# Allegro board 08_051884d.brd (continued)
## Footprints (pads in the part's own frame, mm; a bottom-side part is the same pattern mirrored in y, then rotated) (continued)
CNSMAL554W247H118
  rect 4.521x0.508 smd: 1(-2.261,0)
  rect 5.537x3.607 smd: 2(-2.769,2.261) 3(-2.769,-2.261)
  rect 2.642x6.756 smd: 4(-1.321,0)
CNSMASQ197H161
  rect 0.267x1.295 smd: 1(0,-3.051)
  custom 1.302x1.302 smd: 2(0,2.299)
CNTERCU
  rect 2.616x0.889 smd: 1(0,0)
DFN10_3X3_PAD2_38X1_64
  oval 0.254x0.889 smd: 1(-1,-1.555) 2(-0.5,-1.555) 3(0,-1.555) 4(0.5,-1.555) 5(1,-1.555) 6(1,1.555) 7(0.5,1.555) 8(0,1.555) 9(-0.5,1.555) 10(-1,1.555)
  rect 2.388x1.651 smd: PAD(0,0)
DIOSMJ5_0
  rect 2.286x1.88 smd: A(2.164,0) C(-2.164,0)
DQFN16_3_5X2_5_PAD2_15X1_15
  oval 0.889x0.229 smd: 1(-1.795,-0.25) 8(1.795,-0.25) 9(1.795,0.25) 16(-1.795,0.25)
  oval 0.229x0.889 smd: 2(-1.25,-1.294) 3(-0.75,-1.294) 4(-0.25,-1.294) 5(0.25,-1.294) 6(0.75,-1.294) 7(1.25,-1.294) 10(1.25,1.294) 11(0.75,1.294) 12(0.25,1.294) 13(-0.25,1.294) 14(-0.75,1.294) 15(-1.25,1.294)
  rect 1.905x0.991 smd: PAD(0,0)
F1206
  rect 1.143x2.032 smd: 1(-1.333,0) 2(1.333,0)
JUMPER0603_3P
  rect 1.194x1.092 smd: 1(-1.694,0) 2(0,0) 3(1.694,0)
L0201
  rect 0.178x0.33 smd: 1(-0.203,0) 2(0.203,0)
L0402
  rect 0.584x0.711 smd: 1(-0.475,0) 2(0.475,0)
L0603H28
  rect 1.041x0.991 smd: 1(-0.75,0) 2(0.75,0)
LCC4H210
  rect 1.27x2.286 smd: 1(-2.54,-3.556) 2(2.54,-3.556) 3(2.54,3.556) 4(-2.54,3.556)
LED0402_A
  rect 0.711x0.508 smd: A(0.555,0) C(-0.555,0)
LFBGA324
  round 0.356 smd: A1(-6.8,-6.8) A2(-6.8,-6) A3(-6.8,-5.2) A4(-6.8,-4.4) A5(-6.8,-3.6) A6(-6.8,-2.8) A7(-6.8,-2) A8(-6.8,-1.2) A9(-6.8,-0.4) A10(-6.8,0.4) A11(-6.8,1.2) A12(-6.8,2) A13(-6.8,2.8) A14(-6.8,3.6) A15(-6.8,4.4) A16(-6.8,5.2) A17(-6.8,6) A18(-6.8,6.8) B1(-6,-6.8) B2(-6,-6) B3(-6,-5.2) B4(-6,-4.4) B5(-6,-3.6) B6(-6,-2.8) B7(-6,-2) B8(-6,-1.2) B9(-6,-0.4) B10(-6,0.4) B11(-6,1.2) B12(-6,2) B13(-6,2.8) B14(-6,3.6) B15(-6,4.4) B16(-6,5.2) B17(-6,6) B18(-6,6.8) C1(-5.2,-6.8) C2(-5.2,-6) C3(-5.2,-5.2) C4(-5.2,-4.4) C5(-5.2,-3.6) C6(-5.2,-2.8) C7(-5.2,-2) C8(-5.2,-1.2) C9(-5.2,-0.4) C10(-5.2,0.4) C11(-5.2,1.2) C12(-5.2,2) C13(-5.2,2.8) C14(-5.2,3.6) C15(-5.2,4.4) C16(-5.2,5.2) C17(-5.2,6) C18(-5.2,6.8) D1(-4.4,-6.8) D2(-4.4,-6) D3(-4.4,-5.2) D4(-4.4,-4.4) D5(-4.4,-3.6) D6(-4.4,-2.8) D7(-4.4,-2) D8(-4.4,-1.2) D9(-4.4,-0.4) D10(-4.4,0.4) D11(-4.4,1.2) D12(-4.4,2) D13(-4.4,2.8) D14(-4.4,3.6) D15(-4.4,4.4) D16(-4.4,5.2) D17(-4.4,6) D18(-4.4,6.8) E1(-3.6,-6.8) E2(-3.6,-6) E3(-3.6,-5.2) E4(-3.6,-4.4) E5(-3.6,-3.6) E6(-3.6,-2.8) E7(-3.6,-2) E8(-3.6,-1.2) E9(-3.6,-0.4) E10(-3.6,0.4) E11(-3.6,1.2) E12(-3.6,2) E13(-3.6,2.8) E14(-3.6,3.6) E15(-3.6,4.4) E16(-3.6,5.2) E17(-3.6,6) E18(-3.6,6.8) F1(-2.8,-6.8) F2(-2.8,-6) F3(-2.8,-5.2) F4(-2.8,-4.4) F5(-2.8,-3.6) F6(-2.8,-2.8) F7(-2.8,-2) F8(-2.8,-1.2) F9(-2.8,-0.4) F10(-2.8,0.4) F11(-2.8,1.2) F12(-2.8,2) F13(-2.8,2.8) F14(-2.8,3.6) F15(-2.8,4.4) F16(-2.8,5.2) F17(-2.8,6) F18(-2.8,6.8) G1(-2,-6.8) G2(-2,-6) G3(-2,-5.2) G4(-2,-4.4) G5(-2,-3.6) G6(-2,-2.8) G7(-2,-2) G8(-2,-1.2) G9(-2,-0.4) G10(-2,0.4) G11(-2,1.2) G12(-2,2) G13(-2,2.8) G14(-2,3.6) G15(-2,4.4) G16(-2,5.2) G17(-2,6) G18(-2,6.8) H1(-1.2,-6.8) H2(-1.2,-6) H3(-1.2,-5.2) H4(-1.2,-4.4) H5(-1.2,-3.6) H6(-1.2,-2.8) H7(-1.2,-2) H8(-1.2,-1.2) H9(-1.2,-0.4) H10(-1.2,0.4) H11(-1.2,1.2) H12(-1.2,2) H13(-1.2,2.8) H14(-1.2,3.6) H15(-1.2,4.4) H16(-1.2,5.2) H17(-1.2,6) H18(-1.2,6.8) J1(-0.4,-6.8) J2(-0.4,-6) J3(-0.4,-5.2) J4(-0.4,-4.4) J5(-0.4,-3.6) J6(-0.4,-2.8) J7(-0.4,-2) J8(-0.4,-1.2) J9(-0.4,-0.4) J10(-0.4,0.4) J11(-0.4,1.2) J12(-0.4,2) J13(-0.4,2.8) J14(-0.4,3.6) J15(-0.4,4.4) J16(-0.4,5.2) J17(-0.4,6) J18(-0.4,6.8) K1(0.4,-6.8) K2(0.4,-6) K3(0.4,-5.2) K4(0.4,-4.4) K5(0.4,-3.6) K6(0.4,-2.8) K7(0.4,-2) K8(0.4,-1.2) K9(0.4,-0.4) K10(0.4,0.4) K11(0.4,1.2) K12(0.4,2) K13(0.4,2.8) K14(0.4,3.6) K15(0.4,4.4) K16(0.4,5.2) K17(0.4,6) K18(0.4,6.8) L1(1.2,-6.8) L2(1.2,-6) L3(1.2,-5.2) L4(1.2,-4.4) L5(1.2,-3.6) L6(1.2,-2.8) L7(1.2,-2) L8(1.2,-1.2) L9(1.2,-0.4) L10(1.2,0.4) L11(1.2,1.2) L12(1.2,2) L13(1.2,2.8) L14(1.2,3.6) L15(1.2,4.4) L16(1.2,5.2) L17(1.2,6) L18(1.2,6.8) M1(2,-6.8) M2(2,-6) M3(2,-5.2) M4(2,-4.4) M5(2,-3.6) M6(2,-2.8) M7(2,-2) M8(2,-1.2) M9(2,-0.4) M10(2,0.4) M11(2,1.2) M12(2,2) M13(2,2.8) M14(2,3.6) M15(2,4.4) M16(2,5.2) M17(2,6) M18(2,6.8) N1(2.8,-6.8) N2(2.8,-6) N3(2.8,-5.2) N4(2.8,-4.4) N5(2.8,-3.6) N6(2.8,-2.8) N7(2.8,-2) N8(2.8,-1.2) N9(2.8,-0.4) N10(2.8,0.4) N11(2.8,1.2) N12(2.8,2) N13(2.8,2.8) N14(2.8,3.6) N15(2.8,4.4) N16(2.8,5.2) N17(2.8,6) N18(2.8,6.8) P1(3.6,-6.8) P2(3.6,-6) P3(3.6,-5.2) P4(3.6,-4.4) P5(3.6,-3.6) P6(3.6,-2.8) P7(3.6,-2) P8(3.6,-1.2) P9(3.6,-0.4) P10(3.6,0.4) P11(3.6,1.2) P12(3.6,2) P13(3.6,2.8) P14(3.6,3.6) P15(3.6,4.4) P16(3.6,5.2) P17(3.6,6) P18(3.6,6.8) R1(4.4,-6.8) R2(4.4,-6) R3(4.4,-5.2) R4(4.4,-4.4) R5(4.4,-3.6) R6(4.4,-2.8) R7(4.4,-2) R8(4.4,-1.2) R9(4.4,-0.4) R10(4.4,0.4) R11(4.4,1.2) R12(4.4,2) R13(4.4,2.8) R14(4.4,3.6) R15(4.4,4.4) R16(4.4,5.2) R17(4.4,6) R18(4.4,6.8) T1(5.2,-6.8) T2(5.2,-6) T3(5.2,-5.2) T4(5.2,-4.4) T5(5.2,-3.6) T6(5.2,-2.8) T7(5.2,-2) T8(5.2,-1.2) T9(5.2,-0.4) T10(5.2,0.4) T11(5.2,1.2) T12(5.2,2) T13(5.2,2.8) T14(5.2,3.6) T15(5.2,4.4) T16(5.2,5.2) T17(5.2,6) T18(5.2,6.8) U1(6,-6.8) U2(6,-6) U3(6,-5.2) U4(6,-4.4) U5(6,-3.6) U6(6,-2.8) U7(6,-2) U8(6,-1.2) U9(6,-0.4) U10(6,0.4) U11(6,1.2) U12(6,2) U13(6,2.8) U14(6,3.6) U15(6,4.4) U16(6,5.2) U17(6,6) U18(6,6.8) V1(6.8,-6.8) V2(6.8,-6) V3(6.8,-5.2) V4(6.8,-4.4) V5(6.8,-3.6) V6(6.8,-2.8) V7(6.8,-2) V8(6.8,-1.2) V9(6.8,-0.4) V10(6.8,0.4) V11(6.8,1.2) V12(6.8,2) V13(6.8,2.8) V14(6.8,3.6) V15(6.8,4.4) V16(6.8,5.2) V17(6.8,6) V18(6.8,6.8)
LGA43
  rect 0.356x0.432 smd: 1(-2.375,-2.25) 2(-1.875,-2.25) 3(-1.375,-2.25) 4(-0.875,-2.25) 5(-0.375,-2.25) 6(0.125,-2.25) 7(0.625,-2.25) 8(1.125,-2.25) 9(1.625,-2.25) 20(1.625,2.25) 21(1.125,2.25) 22(0.625,2.25) 23(0.125,2.25) 24(-0.375,2.25) 25(-0.875,2.25) 26(-1.375,2.25) 27(-1.875,2.25) 28(-2.375,2.25)
  rect 0.762x0.356 smd: 10(2.3,-2.25) 11(2.3,-1.75) 12(2.3,-1.25) 13(2.3,-0.75) 14(2.3,-0.25) 15(2.3,0.25) 16(2.3,0.75) 17(2.3,1.25) 18(2.3,1.75) 19(2.3,2.25)
  rect 0.864x0.254 smd: 29(-2.21,1.675) 30(-1.16,1.675) 31(-0.11,1.675) 41(-2.21,-1.675) 42(-1.16,-1.675) 43(-0.11,-1.675)
  rect 0.864x0.508 smd: 32(-2.21,0.925) 33(-1.16,0.925) 34(-0.11,0.925) 38(-2.21,-0.925) 39(-1.16,-0.925) 40(-0.11,-0.925)
  rect 0.864x0.61 smd: 35(-2.21,0) 36(-1.16,0) 37(-0.11,0)
LSML208W216H122_A
  rect 1.168x4.648 smd: 1(-1.651,0) 2(1.651,0)
LSMSQ157H122
  rect 0.965x3.708 smd: 1(-1.181,0) 2(1.181,0)
NF1846-1
  custom 0.445x0.445 smd: 1(0,0)
  rect 0.711x0.356 smd: 2(-0.914,0) 4(0.914,0.711) 6(0.914,-0.711)
  round 0.127 smd: 3(-1.016,0.711) 5(1.041,0)
QFN8_3X3_PAD2_44X1_7
  oval 0.305x0.914 smd: 1(-0.75,-1.557) 2(-0.25,-1.557) 3(0.25,-1.557) 4(0.75,-1.557) 5(0.75,1.557) 6(0.25,1.557) 7(-0.25,1.557) 8(-0.75,1.557)
  rect 2.438x1.702 smd: PAD(0,0)
QFN16_3X3_PAD1_7X1_7
  oval 0.305x0.787 smd: 1(-0.75,-1.5) 2(-0.25,-1.5) 3(0.25,-1.5) 4(0.75,-1.5) 9(0.75,1.5) 10(0.25,1.5) 11(-0.25,1.5) 12(-0.75,1.5)
  oval 0.787x0.305 smd: 5(1.5,-0.75) 6(1.5,-0.25) 7(1.5,0.25) 8(1.5,0.75) 13(-1.5,0.75) 14(-1.5,0.25) 15(-1.5,-0.25) 16(-1.5,-0.75)
  rect 1.702x1.702 smd: PAD(0,0)
QFN40_6X6_PAD3_9X3_9
  oval 0.305x0.838 smd: 1(-2.25,-2.95) 2(-1.75,-2.95) 3(-1.25,-2.95) 4(-0.75,-2.95) 5(-0.25,-2.95) 6(0.25,-2.95) 7(0.75,-2.95) 8(1.25,-2.95) 9(1.75,-2.95) 10(2.25,-2.95) 21(2.25,2.95) 22(1.75,2.95) 23(1.25,2.95) 24(0.75,2.95) 25(0.25,2.95) 26(-0.25,2.95) 27(-0.75,2.95) 28(-1.25,2.95) 29(-1.75,2.95) 30(-2.25,2.95)
  oval 0.838x0.305 smd: 11(2.95,-2.25) 12(2.95,-1.75) 13(2.95,-1.25) 14(2.95,-0.75) 15(2.95,-0.25) 16(2.95,0.25) 17(2.95,0.75) 18(2.95,1.25) 19(2.95,1.75) 20(2.95,2.25) 31(-2.95,2.25) 32(-2.95,1.75) 33(-2.95,1.25) 34(-2.95,0.75) 35(-2.95,0.25) 36(-2.95,-0.25) 37(-2.95,-0.75) 38(-2.95,-1.25) 39(-2.95,-1.75) 40(-2.95,-2.25)
  rect 3.912x3.912 smd: PAD(0,0)
QFN68_10X10_PAD6_3X6_3
  oval 0.254x1.041 smd: 1(-4,-4.851) 2(-3.5,-4.851) 3(-3,-4.851) 4(-2.5,-4.851) 5(-2,-4.851) 6(-1.5,-4.851) 7(-1,-4.851) 8(-0.5,-4.851) 9(0,-4.851) 10(0.5,-4.851) 11(1,-4.851) 12(1.5,-4.851) 13(2,-4.851) 14(2.5,-4.851) 15(3,-4.851) 16(3.5,-4.851) 17(4,-4.851) 35(4,4.851) 36(3.5,4.851) 37(3,4.851) 38(2.5,4.851) 39(2,4.851) 40(1.5,4.851) 41(1,4.851) 42(0.5,4.851) 43(0,4.851) 44(-0.5,4.851) 45(-1,4.851) 46(-1.5,4.851) 47(-2,4.851) 48(-2.5,4.851) 49(-3,4.851) 50(-3.5,4.851) 51(-4,4.851)
  oval 1.041x0.254 smd: 18(4.851,-4) 19(4.851,-3.5) 20(4.851,-3) 21(4.851,-2.5) 22(4.851,-2) 23(4.851,-1.5) 24(4.851,-1) 25(4.851,-0.5) 26(4.851,0) 27(4.851,0.5) 28(4.851,1) 29(4.851,1.5) 30(4.851,2) 31(4.851,2.5) 32(4.851,3) 33(4.851,3.5) 34(4.851,4) 52(-4.851,4) 53(-4.851,3.5) 54(-4.851,3) 55(-4.851,2.5) 56(-4.851,2) 57(-4.851,1.5) 58(-4.851,1) 59(-4.851,0.5) 60(-4.851,0) 61(-4.851,-0.5) 62(-4.851,-1) 63(-4.851,-1.5) 64(-4.851,-2) 65(-4.851,-2.5) 66(-4.851,-3) 67(-4.851,-3.5) 68(-4.851,-4)
  rect 6.299x6.299 smd: PAD(0,0)
R0201
  rect 0.305x0.406 smd: 1(-0.318,0) 2(0.318,0)
R0402
  rect 0.635x0.737 smd: 1(-0.5,0) 2(0.5,0)
R0603
  rect 0.787x0.991 smd: 1(-0.85,0) 2(0.85,0)
R0805
  rect 1.041x1.397 smd: 1(-0.95,0) 2(0.95,0)
R1206
  rect 1.041x1.753 smd: 1(-1.5,0) 2(1.5,0)
R1210
  rect 1.575x2.692 smd: 1(-1.397,0) 2(1.397,0)
R2512H35
  rect 2.108x3.988 smd: 1(-3.104,0) 2(3.104,0)
SOT23
  rect 1.016x1.397 smd: 1(-0.94,-1.118) 2(0.94,-1.118) 3(0,1.118)
SWSMSQ197H165-2
  rect 1.27x1.27 smd: 1A(-2.75,-1.27) 1B(2.75,-1.27) 2A(-2.75,1.27) 2B(2.75,1.27)
TPSMC30
  round 0.762 smd: 1(0,0)
TSML63W31H29
  rect 0.254x0.559 smd: 1(-0.508,-0.394) 2(0,-0.394) 3(0.508,-0.394) 4(0.508,0.394) 5(0,0.394) 6(-0.508,0.394)
TSML150W160H160
  rect 0.762x1.651 smd: 1(-1.27,1.587) 2(0,1.587) 3(1.27,1.587) 4(1.27,-1.587) 5(0,-1.587) 6(-1.27,-1.587)
TSSOP8
  rect 0.33x1.651 smd: 1(-0.975,-2.92) 2(-0.325,-2.92) 3(0.325,-2.92) 4(0.975,-2.92) 5(0.975,2.92) 6(0.325,2.92) 7(-0.325,2.92) 8(-0.975,2.92)
unnamed#2
  round 3.937 hole 2.667 unplated: (0,0)
UQFN12_2X1_7
  custom 0.102x0.102 smd: 1(-0.8,-0.655)
  rect 0.203x0.61 smd: 2(-0.4,-0.655) 3(0,-0.655) 4(0.4,-0.655) 5(0.8,-0.655) 7(0.8,0.655) 8(0.4,0.655) 9(0,0.655) 10(-0.4,0.655) 11(-0.8,0.655)
  rect 0.61x0.203 smd: 6(0.805,0) 12(-0.805,0)
WLCSP6_B
  round 0.203 smd: A1(-0.4,-0.2) A2(-0.4,0.2) B1(0,-0.2) B2(0,0.2) C1(0.4,-0.2) C2(0.4,0.2)
YSML276W197H63
  rect 1.956x1.778 smd: 1(-2.54,-1.83) 2(0,-1.83) 3(2.54,-1.83) 4(2.54,1.83) 5(0,1.83) 6(-2.54,1.83)

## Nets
AVDD1: C2AA.1 C5AA.1 C8AA.1 C11AA.1 C12N.1 C14AA.1 C17AA.1 C48AA.1 C50AA.1 E4NN.2(N2) U1AA.D2 U1AA.D3 U1AA.D4 U1AA.E3 U1AA.F3 U1AA.N3 U1AA.P3 U1AA.R2 U1AA.R3 U1AA.R4
AVDD1_ADC: C7NN.1 C30AA.1 C32AA.1 C35AA.1 C38AA.1 E2NN.2(N2) U1AA.G7 U1AA.G8 U1AA.M7 U1AA.M8
AVDD2: C1AA.1 C4AA.1 C7AA.1 C10AA.1 C13AA.1 C16.1 C16AA.1 E1.2(N2) U1AA.A2 U1AA.E2 U1AA.H2 U1AA.L2 U1AA.L3 U1AA.P2 U1AA.V2
DVDD1: C9M.1 C41AA.1 C43AA.1 C45AA.1 C46AA.1 C47AA.1 C49AA.1 C70AA.1 E1M.2(N2) U1AA.F10 U1AA.H9 U1AA.H11 U1AA.J9 U1AA.J11 U1AA.K9 U1AA.K11 U1AA.L9 U1AA.L11 U1AA.M9
DVDD1P0_SNS: R8M.2(N2) U1M.13
DVDD1P0V_ADJ: R4M.1 U1M.8
DVDD1P0V_EN: R2M.2(N2) R3M.1 U1M.16
DVDD1P0V_REF: C5M.1 U1M.5
DVDD1P0V_REG: C4M.1 U1M.6(VREG)
DVDD1P0V_SS: C6M.1 U1M.14
GND_SIGNAL: ADC0.2 ADC0.3 ADC0.4(SH3) ADC1.2 ADC1.3 ADC1.4(SH3) ADC2.2 ADC2.3 ADC2.4(SH3) ADC3.2 ADC3.3 ADC3.4(SH3) ADC_CLK.2(SHIELD) AGC.13 AGC.14 AGC.15 AGC.16(N8) C1.2(N2) C1AA.2(N2) C1B.2(N2) C1FF.1 C1K.2(N2) C1LL.2(N2) C1X.2(N2) C2.2(N2) C2A.2(N2) C2AA.2(N2) C2B.2(N2) C2FF.1 C2LL.2(N2) C2M.2(N2) C2NN.2(N2) C2P.2(N2) C2Q.2(N2) C2XA.2(N2) C3.2(N2) C3B.2(N2) C3FF.1 C3LL.2(N2) C3M.2(N2) C3NN.2(N2) C3P.2(N2) C4.2(N2) C4AA.2(N2) C4B.2(N2) C4FF.2(N2) C4LL.2(N2) C4M.2(N2) C4NN.2(N2) C4P.2(N2) C4Q.2(N2) C4X.2(N2) C5.2(N2) C5AA.2(N2) C5B.2(N2) C5FF.2(N2) C5LL.2(N2) C5M.2(N2) C5NN.2(N2) C5OO.2(N2) C5P.2(N2) C5Q.2(N2) C5X.2(N2) C6.2(N2) C6AA.2(N2) C6B.2(N2) C6FF.2(N2) C6LL.2(N2) C6M.2(N2) C6NN.2(N2) C6OO.2(N2) C6P.2(N2) C6Q.2(N2) C6X.2(N2) C7.2(N2) C7AA.2(N2) C7B.2(N2) C7LL.2(N2) C7M.2(N2) C7NN.2(N2) C7OO.2(N2) C7P.2(N2) C7X.2(N2) C8.2(N2) C8AA.2(N2) C8B.2(N2) C8FF.1 C8LL.2(N2) C8M.2(N2) C8NN.2(N2) C8OO.2(N2) C8P.2(N2) C8X.2(N2) C9.2(N2) C9AA.2(N2) C9B.2(N2) C9FF.1 C9LL.2(N2) C9M.2(N2) C9NN.2(N2) C9OO.2(N2) C9P.2(N2) C9X.2(N2) C10AA.2(N2) C10B.2(N2) C10FF.2(N2) C10LL.2(N2) C10NN.2(N2) C10X.2(N2) C11AA.2(N2) C11FF.2(N2) C12.2(N2) C12AA.2(N2) C12FF.1 C12N.2(N2) C13.2(N2) C13AA.2(N2) C13FF.1 C14.2(N2) C14AA.2(N2) C14FF.1 C14OO.2(N2) C15.2(N2) C15AA.2(N2) C15FF.2(N2) C16.2(N2) C16AA.2(N2) C16B.1 C16FF.2(N2) C17.2(N2) C17AA.2(N2) C17FF.2(N2) C17OO.2(N2) C18.2(N2) C18AA.2(N2) C18B.2(N2) C18FF.1 C19.2(N2) C19AA.2(N2) C19B.2(N2) C19FF.2(N2) C20.2(N2) C20AA.2(N2) C20B.1 C21AA.2(N2) C21B.1 C22AA.2(N2) C22B.1 C22LL.2(N2) C23AA.2(N2) C23B.1 C23LL.2(N2) C23X.2(N2) C24AA.2(N2) C24B.1 C24LL.2(N2) C25AA.2(N2) C25B.1 C25LL.2(N2) C26B.2(N2) C27AA.2(N2) C27B.2(N2) C27LL.2(N2) C28B.2(N2) C28LL.2(N2) C29AA.2(N2) C29LL.2(N2) C30AA.2(N2) C30LL.2(N2) C31AA.2(N2) C31LL.2(N2) C32AA.2(N2) C33AA.2(N2) C34AA.2(N2) C35AA.2(N2) C36AA.2(N2) C37AA.2(N2) C38AA.2(N2) C39AA.2(N2) C40AA.2(N2) C40LL.2(N2) C41AA.2(N2) C41B.2(N2) C41LL.2(N2) C42AA.2(N2) C42LL.2(N2) C43AA.2(N2) C43B.2(N2) C43LL.2(N2) C44AA.2(N2) C45AA.2(N2) C46AA.2(N2) C47AA.2(N2) C48AA.2(N2) C49AA.2(N2) C50AA.2(N2) C51AA.2(N2) C52AA.2(N2) C53AA.2(N2) C54AA.2(N2) C55AA.2(N2) C56AA.2(N2) C57AA.2(N2) C58AA.2(N2) C59AA.2(N2) C60AA.2(N2) C69AA.2(N2) C70AA.2(N2) C71AA.2(N2) C72AA.2(N2) C100.2(N2) D1A.A(P) DAC0.2 DAC0.3 DAC0.4(SH3) DAC1.2 DAC1.3 DAC1.4(SH3) DAC2.2 DAC2.3 DAC2.4(SH3) DAC3.2 DAC3.3 DAC3.4(SH3) DS1P.C DS100.C EXT_CLK.2 EXT_CLK.3 EXT_CLK.4(SH3) EXT_HMCREF.2(SHIELD) EXT_SYNC.2(SHIELD) EXT_SYS_N.2(SHIELD) EXT_SYS_P.2(SHIELD) GND0.1(N1) GND1.1(N1) GND2.1(N1) GND3.1(N1) GPIO.14 GPIO.15 GPIO.16(N8) P1.2(N2) P1AA.2 P1AA.3(N3) P1K.A1 P1K.A4 P1K.A5 P1K.A8 P1K.A9 P1K.A12 P1K.A13 P1K.A16 P1K.A17 P1K.A20 P1K.A21 P1K.A24 P1K.A25 P1K.A28 P1K.A29 P1K.A32 P1K.A33 P1K.A36 P1K.A37 P1K.A40 P1K.B1 P1K.B2 P1K.B3 P1K.B6 P1K.B7 P1K.B10 P1K.B11 P1K.B14 P1K.B15 P1K.B18 P1K.B19 P1K.B22 P1K.B23 P1K.B26 P1K.B27 P1K.B30 P1K.B31 P1K.B34 P1K.B35 P1K.B38 P1K.B39 P1K.C1 P1K.C4 P1K.C5 P1K.C8 P1K.C9 P1K.C12 P1K.C13 P1K.C16 P1K.C17 P1K.C20 P1K.C21 P1K.C24 P1K.C25 P1K.C28 P1K.C29 P1K.C32 P1K.C33 P1K.C36 P1K.C38 P1K.C40 P1K.D2 P1K.D3 P1K.D6 P1K.D7 P1K.D10 P1K.D13 P1K.D16 P1K.D19 P1K.D22 P1K.D25 P1K.D28 P1K.D37 P1K.D39 P1K.E1 P1K.E4 P1K.E5 P1K.E8 P1K.E11 P1K.E14 P1K.E17 P1K.E20 P1K.E23 P1K.E26 P1K.E29 P1K.E32 P1K.E35 P1K.E38 P1K.E40 P1K.F2 P1K.F3 P1K.F6 P1K.F9 P1K.F12 P1K.F15 P1K.F18 P1K.F21 P1K.F24 P1K.F27 P1K.F30 P1K.F33 P1K.F36 P1K.F39 P1K.G1 P1K.G4 P1K.G5 P1K.G8 P1K.G11 P1K.G14 P1K.G17 P1K.G20 P1K.G23 P1K.G26 P1K.G29 P1K.G32 P1K.G35 P1K.G38 P1K.G40 P1K.H2 P1K.H3 P1K.H6 P1K.H9 P1K.H12 P1K.H15 P1K.H18 P1K.H21 P1K.H24 P1K.H27 P1K.H30 P1K.H33 P1K.H36 P1K.H39 P1K.J1 P1K.J2 P1K.J4 P1K.J5 P1K.J8 P1K.J11 P1K.J14 P1K.J17 P1K.J20 P1K.J23 P1K.J26 P1K.J29 P1K.J32 P1K.J35 P1K.J38 P1K.J40 P1K.K2 P1K.K3 P1K.K6 P1K.K9 P1K.K12 P1K.K15 P1K.K18 P1K.K21 P1K.K24 P1K.K27 P1K.K30 P1K.K33 P1K.K36 P1K.K39 Q1M.2(S) Q1NN.2(S) Q1Q.2(S) Q1X.2(S) R1A.2(N2) R1K.2(N2) R2AA.2(N2) R2LL.2(N2) R3B.2(N2) R3FF.2(N2) R3M.2(N2) R3P.2(N2) R4B.2(N2) R4LL.2(N2) R4M.2(N2) R4NN.2(N2) R4X.2(N2) R5B.2(N2) R5FF.2(N2) R6B.2(N2) R6P.2(N2) R7FF.2(N2) R7Q.2(N2) R8LL.2(N2) R9LL.2(N2) R10Q.2(N2) R11AA.2(N2) R11LL.2(N2) R12LL.2(N2) R13FF.2(N2) R15FF.2(N2) R16LL.2(N2) R17FF.2(N2) R18LL.2(N2) R19FF.2(N2) R21FF.2(N2) R21LL.1 R23.2(N2) R26.1 R29.2(N2) R30.2(N2) R31.2(N2) R34FF.2(N2) RESET.2A RESET.2B(N4) T1.2 T1D.1 T1D.3 T1D.5 T1R.1 T1R.2 T1S.1 T1S.2 T1T.1 T1T.2 T1U.1 T1U.2 T1V.1 T1V.2 T1W.1 T1W.2 T1X.1 T1X.2 T1Y.1 T1Y.2 T1Z.1 T1Z.2 T2.2 T3.2 T3.5 T4.2 T5.2 T6.2 T6.5 T7.2 T7.5 T8.2 T8.5 T9.2 T9.5 T10.2 T10.5 T11.2 T11.5 T12.2 T12.5 TP2A.1(N1) TP6.1(N1) TP9.1(N1) TP10K.1(N1) TP14K.1(N1) TP15K.1(N1) TP16K.1(N1) TP17K.1(N1) TP18K.1(N1) U1.5 U1.8 U1.21 U1.29 U1.33 U1.37 U1.40 U1.PAD U1AA.A1 U1AA.A3 U1AA.A4 U1AA.A7 U1AA.A8 U1AA.A11 U1AA.A17 U1AA.A18 U1AA.B2 U1AA.B3 U1AA.B4 U1AA.B5 U1AA.B6 U1AA.B9 U1AA.B10 U1AA.B14 U1AA.B15 U1AA.C2 U1AA.C5 U1AA.C6 U1AA.C7 U1AA.C8 U1AA.C11 U1AA.C17 U1AA.C18 U1AA.D1 U1AA.D5 U1AA.D9 U1AA.D14 U1AA.D15 U1AA.E1 U1AA.E4 U1AA.E6 U1AA.E17 U1AA.E18 U1AA.F2 U1AA.F4 U1AA.F6 U1AA.F7 U1AA.F8 U1AA.F14 U1AA.F15 U1AA.G2 U1AA.G3 U1AA.G4 U1AA.G5 U1AA.G9 U1AA.G17 U1AA.G18 U1AA.H1 U1AA.H5 U1AA.H6 U1AA.H7 U1AA.H8 U1AA.H10 U1AA.H12 U1AA.H14 U1AA.H15 U1AA.J2 U1AA.J8 U1AA.J10 U1AA.J12 U1AA.J14 U1AA.J15 U1AA.J17 U1AA.J18 U1AA.K2 U1AA.K8 U1AA.K10 U1AA.K12 U1AA.K14 U1AA.K17 U1AA.K18 U1AA.L1 U1AA.L5 U1AA.L6 U1AA.L7 U1AA.L8 U1AA.L10 U1AA.L12 U1AA.L14 U1AA.M2 U1AA.M3 U1AA.M4 U1AA.M5 U1AA.M10 U1AA.M17 U1AA.M18 U1AA.N2 U1AA.N4 U1AA.N6 U1AA.N7 U1AA.N8 U1AA.N10 U1AA.N14 U1AA.N15 U1AA.P1 U1AA.P4 U1AA.P6 U1AA.P17 U1AA.P18 U1AA.R1 U1AA.R5 U1AA.R9 U1AA.R14 U1AA.R15 U1AA.T2 U1AA.T5 U1AA.T6 U1AA.T7 U1AA.T8 U1AA.T11 U1AA.T17 U1AA.T18 U1AA.U2 U1AA.U3 U1AA.U4 U1AA.U5 U1AA.U6 U1AA.U9 U1AA.U10 U1AA.U14 U1AA.U15 U1AA.V1 U1AA.V3 U1AA.V4 U1AA.V7 U1AA.V8 U1AA.V11 U1AA.V17 U1AA.V18 U1B.35 U1B.PAD U1FF.2 U1FF.7 U1FF.8 U1FF.10 U1FF.PAD U1K.4 U1K.7(WC_N) U1LL.8 U1LL.14 U1LL.35 U1LL.36 U1LL.37 U1M.7 U1M.PAD U1NN.7 U1NN.PAD U1P.4 U1P.PAD U1Q.3 U1Q.6 U1Q.PAD U1X.7 U1X.PAD U2FF.2 U2FF.7 U2FF.8 U2FF.PAD U3.C2 U3FF.2 U3FF.7 U3FF.8 U3FF.10 U3FF.15 U3FF.PAD U4FF.8 U4FF.PAD U5FF.8 U5FF.PAD U6FF.6 U7FF.6 U8FF.6 U8FF.7 U10FF.6 U100.PAD Y1B.3 Y2B.2
1P5V_A: C4LL.1 C5LL.1 C10.2(N2) C42LL.1 L2LL.2(N2) R1.1 R1XA.1 R10LL.2(N2) U1.26 U1.30
1P5V_BST1: C11LL.1 U1LL.12
1P5V_BST2: C12LL.2(N2) U1LL.17
1P5V_COMP1: C10LL.1 R51LL.1 U1LL.5
1P5V_COMP2: C2LL.1 R1LL.1 U1LL.24
1P5V_D: C11.2(N2) C23LL.1 C27LL.1 C29LL.1 L1LL.2(N2) R1M.1 R23LL.2(N2) U1.2
1P5V_FB1: R21.1 R21LL.2(N2) R23LL.1 U1LL.4
1P5V_FB2: R4LL.1 R10LL.1 R20.1 U1LL.25
1P5V_RAMP1: R9LL.1 U1LL.3
1P5V_RAMP2: R11LL.1 U1LL.26
1P5V_SW1: C11LL.2(N2) L1LL.1 U1LL.38 U1LL.39 U1LL.40
1P5V_SW2: C12LL.1 L2LL.1 U1LL.32 U1LL.33 U1LL.34
3P3V: 3P3V.1(N1) P1K.C39 P1K.D36 P1K.D38 P1K.D40 R6M.1 R6NN.1 R6X.1
3P3V_BYP: C14OO.1 U100.4
3P3V_HMC: C100.1 E1OO.1 E2OO.1 E3OO.1 R700.1 U100.1 U100.2 U100.3
3P3V_REG: C5OO.1 U100.8(VREG)
3P3VAUX: C1K.1 P1K.D32 TP1K.1(N1) U1K.8
3P8V: C2Q.1 C4Q.1 C22LL.1 C24LL.1 C28LL.1 DS1M.A(P) DS1NN.A(P) DS1Q.A(P) DS1X.A(P) L3LL.2(N2) P1.1 R4Q.1 R6Q.1 R18.1 R22LL.2(N2) R24LL.2(N2) R28.1 U1.34 U1Q.8
3P8V_BST3: C14LL.1 U1LL.13
3P8V_COMP3: C6LL.1 R44LL.1 U1LL.21
3P8V_FB3: C13LL.1 R18LL.1 R24LL.1 U1LL.20
3P8V_RAMP3: R8LL.1 U1LL.19
3P8V_RC: C13LL.2(N2) R22LL.1
3P8V_SW3: C14LL.2(N2) L3LL.1 U1LL.15
12P0V_1: 12P0V.1(N1) C1A.1 C1LL.1 C2A.1 C3LL.1 C7LL.1 C13.1 C25LL.1 C30LL.1 C31LL.1 C41LL.1 D1A.C F1A.2(N2) R2.2(N2) R7LL.1 TP1A.1(N1) U1LL.10 U1LL.16 U1LL.29 U1LL.30 U1LL.31 U1LL.41 U1LL.42 U1LL.43 U3.A1 U3.C1
12P0V_FMC: P1K.C35 P1K.C37 R2.1 TP4K.1(N1)
5056_CFG1: R2LL.1 U1LL.28
5056_CFG2: R12LL.1 U1LL.27
5056_MODE: R14LL.2(N2) U1LL.11
5056_RT: R16LL.1 U1LL.6
5056_VREG: C8LL.1 R14LL.1 U1LL.9(VREG)
A1P0V_ADJ: R4NN.1 U1NN.8
A1P0V_INN: C2NN.1 C3NN.1 R1.2(N2) U1.31 U1NN.1 U1NN.2 U1NN.3 U1NN.4 U1NN.16
A1P0V_REF: C5NN.1 U1NN.5
A1P0V_REG: C4NN.1 U1NN.6(VREG)
A1P0V_SNS: C9NN.1 C10NN.1 E1NN.1 E2NN.1 E4NN.1 R22.1 U1.32 U1NN.9 U1NN.10 U1NN.11 U1NN.12 U1NN.13
A1P0V_SS: C8NN.1 U1NN.14
A2P0V_BYP: C4P.1 U1P.3
A2P0V_EN: R2P.2(N2) R3P.1 U1P.7
A2P0V_INP: C2P.1 C3P.1 R2P.1 R18.2(N2) U1.35 U1P.8
A2P0V_REF: C7P.1 R5P.1 U1P.6
A2P0V_REG: C5P.1 U1P.1(VREG)
A2P0V_SNS: R5P.2(N2) R6P.1 U1P.5
AD7175_CS: U1.17 U2FF.3
AD7175_DIN: R12.2(N2) U1.15
AD7175_DOUT: R3.2(N2) R11.2(N2) U1FF.4
AD7175_SCLK: R13.2(N2) U1.16
ADC0: ADC0.1 C3S.2(N2)
ADC1: ADC1.1 C3T.2(N2)
ADC2: ADC2.1 C3U.2(N2)
ADC3: ADC3.1 C3V.2(N2)
ADC_CLK: ADC_CLK.1 C3R.2(N2)
ADC_N0: C1S.1 U1AA.A5
ADC_N1: C2T.1 U1AA.V5
ADC_N2: C2U.1 U1AA.A9
ADC_N3: C2V.1 U1AA.V10
ADC_P0: C2S.1 U1AA.A6
ADC_P1: C1T.1 U1AA.V6
ADC_P2: C1U.1 U1AA.A10
ADC_P3: C1V.1 U1AA.V9
ADCDRV_N: C1R.1 U1AA.C3
ADCDRV_P: C2R.1 U1AA.C4
AGC0_0: AGC.5 U1AA.D12 U4FF.3
AGC0_1: AGC.6 U1AA.D11 U4FF.4
AGC1_0: AGC.7 U1AA.E12 U4FF.5
AGC1_1: AGC.8 U1AA.E11 U4FF.6
AGC2_0: AGC.9 U1AA.F12 U5FF.3
AGC2_1: AGC.10 U1AA.F11 U5FF.4
AGC3_0: AGC.11 U1AA.G12 U5FF.5
AGC3_1: AGC.12 U1AA.G11 U5FF.6
AIN1: C2M.1 C3M.1 R1M.2(N2) R2M.1 R17.1 U1.3 U1M.1 U1M.2 U1M.3 U1M.4
AIN2: C7M.1 C8M.1 E1M.1 JP1.1 R8M.1 R17.2(N2) U1.4 U1M.9 U1M.10 U1M.11 U1M.12
AIN5: C1X.1 C2XA.1 R1XA.2(N2) U1.27 U1X.1 U1X.2 U1X.3 U1X.4 U1X.16
AIN6: C7X.1 C8X.1 E1XX.1 E4X.1 JP1.3 R5X.1 U1.28 U1X.9 U1X.10 U1X.11 U1X.12
AIN14: C6P.1 C8P.1 C9P.1 C51AA.1 E1.1 E2.1 R10.1 U1.36 U1AA.K15 U1P.2
BVDD2: C15.1 C29AA.1 C31AA.1 C34AA.1 C37AA.1 E2.2(N2) U1AA.B11 U1AA.D7 U1AA.E7 U1AA.P7 U1AA.R7 U1AA.U11
BVDD3_0: C24AA.1 U1AA.C10
BVDD3_1: C27AA.1 U1AA.T10
BVNN1_0: C23AA.1 C25AA.1 U1AA.D8 U1AA.E8 U1AA.E9 U1AA.E10
BVNN1_1: C33AA.1 C36AA.1 U1AA.P8 U1AA.P9 U1AA.P10 U1AA.R8
BVNN2_0: C19AA.1 U1AA.C9
BVNN2_1: C21AA.1 U1AA.T9
CLKIN_N: C5D.2(N2) C6D.1 U1AA.K1
CLKIN_P: C3D.2(N2) C4D.1 U1AA.J1
CLKOUT_0_N: C30B.2(N2) P1K.K5
CLKOUT_0_P: C29B.2(N2) P1K.K4
CLKOUT_6_N: C32B.2(N2) P1K.G3
CLKOUT_6_P: C31B.2(N2) P1K.G2
CLKOUT_8_N: C34B.2(N2) P1K.B21
CLKOUT_8_P: C33B.2(N2) P1K.B20
CLKOUT_10_N: C36B.2(N2) P1K.G7
CLKOUT_10_P: C35B.2(N2) P1K.G6
CLKVDD1: C6NN.1 C39AA.1 C40AA.1 E1NN.2(N2) U1AA.G6 U1AA.M6
D1P0V: C10X.1 C52AA.1 C53AA.1 C54AA.1 C55AA.1 C56AA.1 C57AA.1 C58AA.1 C59AA.1 C60AA.1 E2XX.2(N2) U1AA.A16 U1AA.B16 U1AA.C16 U1AA.D16 U1AA.E16 U1AA.F16 U1AA.G16 U1AA.H16 U1AA.J16 U1AA.K16 U1AA.M16 U1AA.N16 U1AA.P16 U1AA.R16 U1AA.T16 U1AA.U16 U1AA.V16
D1P0V_ADJ: R4X.1 U1X.8
D1P0V_REF: C5X.1 U1X.5
D1P0V_REG: C4X.1 U1X.6(VREG)
D1P0V_SNS: R5X.2(N2) U1X.13
D1P0V_SS: C6X.1 U1X.14
D1P8V: AGC.1 AGC.2 AGC.3 AGC.4 C4FF.1 C5FF.1 C5Q.1 C6FF.1 C6Q.1 C9.1 C10FF.1 C11FF.1 C15FF.1 C16FF.1 C17FF.1 C19FF.1 C71AA.1 C72AA.1 GPIO.1 GPIO.2 R2FF.2(N2) R4.1 R4FF.2(N2) R5.1 R6FF.2(N2) R9Q.1 R11FF.1 R12FF.2(N2) R14FF.2(N2) R16FF.2(N2) R18FF.2(N2) R20FF.2(N2) R33FF.2(N2) U1.20 U1AA.C13 U1AA.F9 U1AA.G10 U1AA.T13 U1FF.1 U1FF.15 U1Q.1(VOUT) U2FF.1 U2FF.10 U2FF.15 U3FF.1 U4FF.1 U4FF.2 U4FF.7 U4FF.10 U4FF.15 U5FF.1 U5FF.2 U5FF.7 U5FF.10 U5FF.15 U6FF.1(VL) U7FF.1(VL) U8FF.1(VL) U10FF.1(VL)
D1P8V_EN: R6Q.2(N2) R7Q.1 U1Q.5
D1P8V_FB: R9Q.2(N2) R10Q.1 U1Q.2
D1P8V_PG: Q1Q.1 R4Q.2(N2) U1Q.7
DAC0: C2W.2(N2) DAC0.1
DAC3: C2Z.2(N2) DAC3.1
DAC_N0: R1W.2(N2) T1W.5(SEC_DOT) T9.3 U1AA.C1
DAC_N1: R1X.1 T1X.5(SEC_DOT) T3.3 U1AA.F1
DAC_N2: R1Y.1 T1Y.5(SEC_DOT) T6.3 U1AA.M1
DAC_N3: R1Z.2(N2) T1Z.5(SEC_DOT) T10.3 U1AA.U1
DAC_P0: R1W.1 T1W.4 T9.4 U1AA.B1
DAC_P1: R1X.2(N2) T1X.4 T3.4 U1AA.G1
DAC_P2: R1Y.2(N2) T1Y.4 T6.4 U1AA.N1
DAC_P3: R1Z.1 T1Z.4 T10.4 U1AA.T1
DAVDD1: C9X.1 C15AA.1 C18AA.1 C20AA.1 C22AA.1 E1XX.2(N2) U1AA.D6 U1AA.D10 U1AA.E5 U1AA.F5 U1AA.N5 U1AA.P5 U1AA.R6 U1AA.R10
DCLKVDD1: C3.1 C9AA.1 C12AA.1 C23X.1 C42AA.1 C44AA.1 E4X.2(N2) U1AA.J6 U1AA.J7 U1AA.K5 U1AA.K6 U1AA.K7
EXT_CLK: EXT_CLK.1 T1D.2
EXT_REF: C13B.1 EXT_HMCREF.1 R23.1
EXT_SYNC: EXT_SYNC.1 R2E.2(N2)
EXT_SYS_N: C4C.2(N2) EXT_SYS_N.1
EXT_SYS_P: C2C.2(N2) EXT_SYS_P.1
FPGA_AD7175_CS: P1K.G24 U2FF.14
FPGA_AGC0_0: P1K.D20 U4FF.14
FPGA_AGC0_1: P1K.D21 U4FF.13
FPGA_AGC1_0: P1K.C22 U4FF.12
FPGA_AGC1_1: P1K.C23 U4FF.11
FPGA_AGC2_0: P1K.G21 U5FF.14
FPGA_AGC2_1: P1K.G22 U5FF.13
FPGA_AGC3_0: P1K.H25 U5FF.12
FPGA_AGC3_1: P1K.H26 U5FF.11
FPGA_GPIO0: P1K.H19 U6FF.10
FPGA_GPIO1: P1K.H20 U6FF.9
FPGA_GPIO2: P1K.H22 U6FF.8
FPGA_GPIO3: P1K.H23 U6FF.7
FPGA_GPIO4: P1K.D17 U7FF.10
FPGA_GPIO5: P1K.D18 U7FF.9
FPGA_GPIO6: P1K.C18 U7FF.8
FPGA_GPIO7: P1K.C19 U7FF.7
FPGA_GPIO8: P1K.G18 U8FF.10
FPGA_GPIO9: P1K.G19 U8FF.9
FPGA_GPIO10: P1K.G25 U8FF.8
FPGA_HMC_GPIO1: P1K.H17 U10FF.10
FPGA_IRQB0: P1K.G12 U2FF.13
FPGA_IRQB1: P1K.G13 U2FF.12
FPGA_REFCLK_IN_N: C38B.2(N2) P1K.D5
FPGA_REFCLK_IN_P: C37B.2(N2) P1K.D4
FPGA_RSTB: P1K.H13 R1FF.2(N2) U2FF.11
FPGA_RXEN0: P1K.C14 U3FF.12
FPGA_RXEN1: P1K.C15 U3FF.11
FPGA_SERDIN_N0: C1J.1 P1K.A7
FPGA_SERDIN_N1: C2J.1 P1K.C7
FPGA_SERDIN_N2: C3J.1 P1K.B13
FPGA_SERDIN_N3: C4J.1 P1K.B17
FPGA_SERDIN_N4: C5J.1 P1K.A19
FPGA_SERDIN_N5: C6J.1 P1K.A15
FPGA_SERDIN_N6: C7J.1 P1K.A11
FPGA_SERDIN_N7: C8J.1 P1K.A3
FPGA_SERDIN_P0: C1I.1 P1K.A6
FPGA_SERDIN_P1: C2I.1 P1K.C6
FPGA_SERDIN_P2: C3I.1 P1K.B12
FPGA_SERDIN_P3: C4I.1 P1K.B16
FPGA_SERDIN_P4: C5I.1 P1K.A18
FPGA_SERDIN_P5: C6I.1 P1K.A14
FPGA_SERDIN_P6: C7I.1 P1K.A10
FPGA_SERDIN_P7: C8I.1 P1K.A2
FPGA_SERDOUT_N0: C1H.1 P1K.C3
FPGA_SERDOUT_N1: C2H.1 P1K.A27
FPGA_SERDOUT_N2: C3H.1 P1K.B33
FPGA_SERDOUT_N3: C4H.1 P1K.B37
FPGA_SERDOUT_N4: C5H.1 P1K.A23
FPGA_SERDOUT_N5: C6H.1 P1K.A39
FPGA_SERDOUT_N6: C7H.1 P1K.A35
FPGA_SERDOUT_N7: C8H.1 P1K.A31
FPGA_SERDOUT_P0: C1G.1 P1K.C2
FPGA_SERDOUT_P1: C2G.1 P1K.A26
FPGA_SERDOUT_P2: C3G.1 P1K.B32
FPGA_SERDOUT_P3: C4G.1 P1K.B36
FPGA_SERDOUT_P4: C5G.1 P1K.A22
FPGA_SERDOUT_P5: C6G.1 P1K.A38
FPGA_SERDOUT_P6: C7G.1 P1K.A34
FPGA_SERDOUT_P7: C8G.1 P1K.A30
FPGA_TXEN0: P1K.D14 U3FF.14
FPGA_TXEN1: P1K.D15 U3FF.13
GA0: P1K.C34 U1K.2
GA1: P1K.D35 U1K.1
GPIO0: GPIO.3 U1AA.N12 U6FF.2
GPIO1: GPIO.4 U1AA.M12 U6FF.3
GPIO2: GPIO.5 U1AA.N11 U6FF.4
GPIO3: GPIO.6 U1AA.M11 U6FF.5
GPIO4: GPIO.7 U1AA.P11 U7FF.2
GPIO5: GPIO.8 U1AA.R11 U7FF.3
GPIO6: GPIO.9 U1AA.N13 U7FF.4
GPIO7: GPIO.10 U1AA.M13 U7FF.5
GPIO8: GPIO.11 U1AA.L13 U8FF.2
GPIO9: GPIO.12 U1AA.K13 U8FF.3
GPIO10: GPIO.13 U1AA.T12 U8FF.4
HMC_3P3V: C6OO.1 C21B.2(N2) C23B.2(N2) C26B.1 C27B.1 E1OO.2(N2) HMC_STATUS.A(P) U1B.17 U1B.26 U1B.57 U1B.68(VCC9_OUT)
HMC_3P3V_PLL: C17OO.1 C22B.2(N2) C24B.2(N2) C25B.2(N2) C28B.1 E2OO.2(N2) U1B.21 U1B.38 U1B.41 U1B.51
HMC_3P3V_VCO: C8OO.1 C20B.2(N2) E1B.1 E2B.1 E3OO.2(N2) U1B.10
HMC_CLK_N: C1D.1 L1D.1 U1B.16
HMC_CLK_P: C1D.2(N2) L2D.1 U1B.15
HMC_CPOUT1: C43B.1 C44B.1 U1B.32 Y2B.1
HMC_GPIO1: U1B.31 U10FF.2
HMC_SCLK: U1B.19 U10FF.5
HMC_SDATA: U1B.20 U10FF.4
HMC_SLEN: U1B.18 U10FF.3
HMC_SYNC: P1K.H14 R1E.1
HMC_SYSREF_N: C3C.1 U1B.14
HMC_SYSREF_P: C1C.1 U1B.13
IRQB0: R4.2(N2) TP1.1(N1) U1AA.P12 U2FF.4
IRQB1: R5.2(N2) TP2.1(N1) U1AA.R12 U2FF.5
PG_C2M: P1K.D1 R14.1 TP13K.1(N1)
PLLCLKVDD1: C6AA.1 R22.2(N2) U1AA.J5
RESETB: R8FF.2(N2) R11FF.2(N2) RESET.1A RESET.1B U1AA.C12
RXEN0: U1AA.E13 U3FF.5
RXEN1: U1AA.D13 U3FF.6
SCL: P1K.C30 TP7K.1(N1) U1K.6
SDA: P1K.C31 TP5K.1(N1) U1K.5
SERDIN_N0: C1H.2(N2) U1AA.L17
SERDIN_N1: C2H.2(N2) U1AA.N17
SERDIN_N2: C3H.2(N2) U1AA.R17
SERDIN_N3: C4H.2(N2) U1AA.U17
SERDIN_N4: C5H.2(N2) U1AA.M14
SERDIN_N5: C6H.2(N2) U1AA.V14
SERDIN_N6: C7H.2(N2) U1AA.T14
SERDIN_N7: C8H.2(N2) U1AA.P14
SERDIN_P0: C1G.2(N2) U1AA.L18
SERDIN_P1: C2G.2(N2) U1AA.N18
SERDIN_P2: C3G.2(N2) U1AA.R18
SERDIN_P3: C4G.2(N2) U1AA.U18
SERDIN_P4: C5G.2(N2) U1AA.M15
SERDIN_P5: C6G.2(N2) U1AA.V15
SERDIN_P6: C7G.2(N2) U1AA.T15
SERDIN_P7: C8G.2(N2) U1AA.P15
SERDOUT_N0: C1J.2(N2) U1AA.A14
SERDOUT_N1: C2J.2(N2) U1AA.C14
SERDOUT_N2: C3J.2(N2) U1AA.E14
SERDOUT_N3: C4J.2(N2) U1AA.G14
SERDOUT_N4: C5J.2(N2) U1AA.H17
SERDOUT_N5: C6J.2(N2) U1AA.F17
SERDOUT_N6: C7J.2(N2) U1AA.D17
SERDOUT_N7: C8J.2(N2) U1AA.B17
SERDOUT_P0: C1I.2(N2) U1AA.A15
SERDOUT_P1: C2I.2(N2) U1AA.C15
SERDOUT_P2: C3I.2(N2) U1AA.E15
SERDOUT_P3: C4I.2(N2) U1AA.G15
SERDOUT_P4: C5I.2(N2) U1AA.H18
SERDOUT_P5: C6I.2(N2) U1AA.F18
SERDOUT_P6: C7I.2(N2) U1AA.D18
SERDOUT_P7: C8I.2(N2) U1AA.B18
SPI0_CSB: P1K.D11 U1FF.14
SPI0_MISO: P1K.D12 U1FF.13
SPI0_MOSI: P1K.H10 U1FF.12
SPI0_SCLK: P1K.H11 U1FF.11
SPI1_CSB: P1K.G15 TP12K.1(N1) U10FF.9
SPI1_SCLK: P1K.H16 TP9K.1(N1) U10FF.7
SPI1_SDIO: P1K.G16 TP3K.1(N1) U10FF.8
SPI_CSB: U1AA.G13 U1FF.3
SPI_SCLK: R7.2(N2) U1AA.H13
SPI_SDIO: R6.2(N2) U1AA.F13
STATUS_LED: HMC_STATUS.C R2B.2(N2)
SYNC_IN: R1E.2(N2) R2E.1 R3B.1 U1B.6
SYNCIN_N0: P1K.D9 U1AA.A13
SYNCIN_N1: P1K.C11 U1AA.A12
SYNCIN_P0: P1K.D8 U1AA.B13
SYNCIN_P1: P1K.C10 U1AA.B12
SYNCOUT_N0: P1K.H8 U1AA.V13
SYNCOUT_N1: P1K.G10 U1AA.V12
SYNCOUT_P0: P1K.H7 U1AA.U13
SYNCOUT_P1: P1K.G9 U1AA.U12
SYSREF2_N: C40B.2(N2) P1K.H5
SYSREF2_P: C39B.2(N2) P1K.H4
SYSREF_N: C3C.2(N2) C4C.1 R1C.2(N2) U1AA.T3
SYSREF_P: C1C.2(N2) C2C.1 R1C.1 U1AA.T4
TXEN0: U1AA.P13 U3FF.3
TXEN1: U1AA.R13(TXEN1) U3FF.4
UNNAMED_5_CAP_I7_N1: C2Z.1 T1Z.3 T10.1(UNBAL)
UNNAMED_5_CAP_I15_N1: C2W.1 T1W.3 T9.1(UNBAL)
UNNAMED_5_CAP_I22_N1: C2Y.1 T1Y.3 T6.1(UNBAL)
UNNAMED_5_CAP_I22_N2: C2Y.2(N2) DAC2.1
UNNAMED_5_CAP_I29_N1: C2X.1 T1X.3 T3.1(UNBAL)
UNNAMED_5_CAP_I29_N2: C2X.2(N2) DAC1.1
UNNAMED_5_CAP_I45_N2: C1S.2(N2) T1S.4 T12.4
UNNAMED_5_CAP_I46_N2: C2S.2(N2) T1S.5(SEC_DOT) T12.3
UNNAMED_5_CAP_I50_N1: C3S.1 T1S.3 T12.1(UNBAL)
UNNAMED_5_CAP_I56_N1: C3T.1 T1T.3 T8.1(UNBAL)
UNNAMED_5_CAP_I59_N2: C2T.2(N2) T1T.5(SEC_DOT) T8.3
UNNAMED_5_CAP_I60_N2: C1T.2(N2) T1T.4 T8.4
UNNAMED_5_CAP_I64_N1: C3U.1 T1U.3 T7.1(UNBAL)
UNNAMED_5_CAP_I67_N2: C2U.2(N2) T1U.5(SEC_DOT) T7.3
UNNAMED_5_CAP_I68_N2: C1U.2(N2) T1U.4 T7.4
UNNAMED_5_CAP_I72_N1: C3V.1 T1V.3 T11.1(UNBAL)
UNNAMED_5_CAP_I75_N2: C2V.2(N2) T1V.5(SEC_DOT) T11.3
UNNAMED_5_CAP_I76_N2: C1V.2(N2) T1V.4 T11.4
UNNAMED_6_ADHMC7044_I49_BGABYP1: C1B.1 U1B.7
UNNAMED_6_ADHMC7044_I49_CLKIN0: C11B.2(N2) U1B.39
UNNAMED_6_ADHMC7044_I49_CLKIN0N: C12B.2(N2) U1B.40
UNNAMED_6_ADHMC7044_I49_CLKOUT0: C29B.1 U1B.1
UNNAMED_6_ADHMC7044_I49_CLKOUT0N: C30B.1 U1B.2
UNNAMED_6_ADHMC7044_I49_CLKOUT6_1: C31B.1 U1B.27
UNNAMED_6_ADHMC7044_I49_CLKOUT6N: C32B.1 U1B.28
UNNAMED_6_ADHMC7044_I49_CLKOUT8_1: C33B.1 U1B.55
UNNAMED_6_ADHMC7044_I49_CLKOUT8N: C34B.1 U1B.56
UNNAMED_6_ADHMC7044_I49_CLKOUT10: C35B.1 U1B.58
UNNAMED_6_ADHMC7044_I49_CLKOUT10N: C36B.1 U1B.59
UNNAMED_6_ADHMC7044_I49_CLKOUT12: C37B.1 U1B.66
UNNAMED_6_ADHMC7044_I49_CLKOUT12N: C38B.1 U1B.67
UNNAMED_6_ADHMC7044_I49_CPOUT2: C41B.1 C42B.1 U1B.50
UNNAMED_6_ADHMC7044_I49_GPIO2: R2B.1 U1B.52
UNNAMED_6_ADHMC7044_I49_LDOBYP2: C2B.1 U1B.8
UNNAMED_6_ADHMC7044_I49_LDOBYP3: C5B.1 U1B.9
UNNAMED_6_ADHMC7044_I49_LDOBYP4: C8B.1 C17B.2(N2) U1B.11
UNNAMED_6_ADHMC7044_I49_LDOBYP5: C17B.1 U1B.12
UNNAMED_6_ADHMC7044_I49_LDOBYP6: C18B.1 U1B.46
UNNAMED_6_ADHMC7044_I49_LDOBYP7: C19B.1 U1B.49
UNNAMED_6_ADHMC7044_I49_OSCIN: C15B.2(N2) U1B.47
UNNAMED_6_ADHMC7044_I49_OSCINN: C16B.2(N2) U1B.48
UNNAMED_6_ADHMC7044_I49_RESET: R4B.1 U1B.5
UNNAMED_6_ADHMC7044_I49_SCLKOUT13: C39B.1 U1B.64
UNNAMED_6_ADHMC7044_I49_SCLKOUT13N: C40B.1 U1B.65
UNNAMED_6_CAP_I18_N1: C15B.1 R1B.2(N2) R25.2(N2)
UNNAMED_6_CAP_I19_N1: C4B.1 C7B.1 C10B.1 E2B.2(N2) Y2B.4(VDD)
UNNAMED_6_CAP_I27_N2: C13B.2(N2) R25.1
UNNAMED_6_CAP_I34_N1: C3B.1 C6B.1 C9B.1 E1B.2(N2) Y1B.6(VDD)
UNNAMED_6_CAP_I36_N1: C12B.1 Y1B.5
UNNAMED_6_CAP_I37_N1: C11B.1 Y1B.4
UNNAMED_6_CAP_I97_N2: C42B.2(N2) R5B.1
UNNAMED_6_CAP_I109_N2: C44B.2(N2) R6B.1
UNNAMED_6_CAP_I146_N1: C2D.2(N2) C3D.1 L2D.2(N2)
UNNAMED_6_CAP_I147_N2: C4D.2(N2) T1D.4
UNNAMED_6_CAP_I152_N1: C2D.1 C5D.1 L1D.2(N2)
UNNAMED_6_CAP_I154_N2: C6D.2(N2) T1D.6(SECP)
UNNAMED_6_CAP_I157_N2: C2R.2(N2) T1R.4
UNNAMED_6_CAP_I160_N2: C1R.2(N2) T1R.5(SEC_DOT)
UNNAMED_6_CAP_I162_N1: C3R.1 T1R.3
UNNAMED_6_RES_I14_N1: R1B.1 Y2B.3
UNNAMED_8_AD71758_I49_AVDD1: C7.1 C8.1 C12.1 U1.9 U1.10 U3.A2(VOUT) U3.B2
UNNAMED_8_AD71758_I49_DOUT: R3.1 U1.14
UNNAMED_8_AD71758_I49_REF: C4.1 U1.39
UNNAMED_8_AD71758_I49_REGCAPA: C1.1 C5.1 U1.7
UNNAMED_8_AD71758_I49_REGCAPD: C2.1 C6.1 U1.22
UNNAMED_8_ADP7112_I50_SS: C14.1 U3.B1
UNNAMED_10_ICFXL4TD245_I9_OEN: R6FF.1 R7FF.1 U3FF.9
UNNAMED_10_ICFXL4TD245_I32_A3: R8FF.1 U2FF.6
UNNAMED_10_ICFXL4TD245_I32_OEN: R4FF.1 R5FF.1 U2FF.9
UNNAMED_10_ICFXL4TD245_I36_A2: R6.1 R12.1 U1FF.5
UNNAMED_10_ICFXL4TD245_I36_A3: R7.1 R13.1 U1FF.6
UNNAMED_10_ICFXL4TD245_I36_OEN: R2FF.1 R3FF.1 U1FF.9
UNNAMED_10_ICFXL4TD245_I68_OEN: R14FF.1 R15FF.1 U5FF.9
UNNAMED_10_ICFXL4TD245_I72_OEN: R12FF.1 R13FF.1 U4FF.9
UNNAMED_10_ICNLSX5014_I91_EN: R20FF.1 R21FF.1 U8FF.12
UNNAMED_10_ICNLSX5014_I104_EN: R18FF.1 R19FF.1 U7FF.12
UNNAMED_10_ICNLSX5014_I107_EN: R16FF.1 R17FF.1 U6FF.12
UNNAMED_10_ICNLSX5014_I128_EN: R33FF.1 R34FF.1 U10FF.12
UNNAMED_12_AD9986V2_I180_DNC1: C20.1 U1AA.B7
UNNAMED_12_AD9986V2_I180_DNC6: C19.1 U1AA.U7
UNNAMED_12_AD9986V2_I180_ISET: R2AA.1 U1AA.H3
UNNAMED_12_AD9986V2_I180_SDO: R11.1 U1AA.J13
UNNAMED_12_AD9986V2_I180_TDP: R11AA.1 U1AA.N9
UNNAMED_12_AD9986V2_I180_VCM0: C18.1 U1AA.B8
UNNAMED_12_AD9986V2_I180_VCM1: C17.1 U1AA.U8
UNNAMED_12_CAP_I55_N1: C62AA.1 R3AA.2(N2)
UNNAMED_13_ADP5056_I64_EN1: R7LL.2(N2) R14.2(N2) U1LL.7 U1LL.18 U1LL.23
UNNAMED_13_CAP_I10_N2: C1A.2(N2) R1A.1
UNNAMED_13_CAP_I38_N1: C40LL.1 R44LL.2(N2)
UNNAMED_13_CAP_I113_N1: C43LL.1 R1LL.2(N2)
UNNAMED_13_CAP_I114_N1: C9LL.1 R51LL.2(N2)
UNNAMED_13_CAP_I134_N1: C11.1 R21.2(N2)
UNNAMED_13_CAP_I136_N1: C10.1 R20.2(N2)
UNNAMED_13_CN3P_I4_N1: F1A.1 P1AA.1
UNNAMED_14_ADP7158_I79_EN: R26.2(N2) R27.2(N2) U100.5
UNNAMED_14_ADP7158_I79_REF: C9OO.1 U100.6 U100.7
UNNAMED_14_ADP7158_I79_VIN1: C7OO.1 R27.1 R28.2(N2) U100.9 U100.10
UNNAMED_14_DIOLED_I76_P: DS100.A(P) R700.2(N2)
UNNAMED_14_DIOLED_I78_N: DS1Q.C R1Q.1
UNNAMED_14_RES_I46_N2: Q1Q.3 R1Q.2(N2)
UNNAMED_15_ADP1765_I17_PG: Q1M.1 R6M.2(N2) R29.1 U1M.15
UNNAMED_15_ADP1765_I48_PG: Q1X.1 R6X.2(N2) R30.1 U1X.15
UNNAMED_15_DIOLED_I75_N: DS1M.C R7M.2(N2)
UNNAMED_15_DIOLED_I76_N: DS1X.C R7X.2(N2)
UNNAMED_15_FERRITE_I56_N1: E2XX.1 JP1.2(COM)
UNNAMED_15_RES_I26_N1: Q1M.3 R7M.1
UNNAMED_15_RES_I61_N1: Q1X.3 R7X.1
UNNAMED_17_ADP1765_I15_PG: Q1NN.1 R6NN.2(N2) R31.1 U1NN.15
UNNAMED_17_DIOLED_I80_P: DS1P.A(P) R10.2(N2)
UNNAMED_17_DIOLED_I84_N: DS1NN.C R7NN.2(N2)
UNNAMED_17_RES_I21_N1: Q1NN.3 R7NN.1
UNNAMED_20_CN400PAKV2_I20_CLK3BIDIRN: P1K.J3 R2K.1
UNNAMED_20_CN400PAKV2_I24_TDI: P1K.D30 P1K.D31
UNNAMED_20_ICM24CXX_I44_E2: R1K.1 U1K.3
VADJ: C1FF.2(N2) C2FF.2(N2) C3FF.2(N2) C8FF.2(N2) C9FF.2(N2) C12FF.2(N2) C13FF.2(N2) C14FF.2(N2) C18FF.2(N2) P1K.E39 P1K.F40 P1K.G39 P1K.H40 R1FF.1 R2K.2(N2) U1FF.16(VCCB) U2FF.16(VCCB) U3FF.16(VCCB) U4FF.16(VCCB) U5FF.16(VCCB) U6FF.11 U7FF.11 U8FF.11 U10FF.11
VCO_COARSE: C63AA.2(N2) U1AA.J4
VCO_FINE: C65AA.1 R3AA.1 U1AA.J3
VCO_VCM: C62AA.2(N2) C63AA.1 C65AA.2(N2) U1AA.K4
VCO_VREG: C69AA.1 U1AA.K3

Pads without a net: P1K B4 B5 B8 B9 B24 B25 B28 B29 B40 C26 C27 D23 D24 D26 D27 D29 D33 D34 E2 E3 E6 E7 E9 E10 E12 E13 E15 E16 E18 E19 E21 E22 E24 E25 E27 E28 E30 E31 E33 E34 E36 E37 F1 F4 F5 F7 F8 F10 F11 F13 F14 F16 F17 F19 F20 F22 F23 F25 F26 F28 F29 F31 F32 F34 F35 F37 F38 G27 G28 G30 G31 G33 G34 G36 G37 H1 H28 H29 H31 H32 H34 H35 H37 H38 J6 J7 J9 J10 J12 J13 J15 J16 J18 J19 J21 J22 J24 J25 J27 J28 J30 J31 J33 J34 J36 J37 J39 K1 K7 K8 K10 K11 K13 K14 K16 K17 K19 K20 K22 K23 K25 K26 K28 K29 K31 K32 K34 K35 K37 K38 K40; R8 1 2; T1 1 3 4 5 6; T1R 6; T1S 6; T1T 6; T1U 6; T1V 6; T1W 6; T1X 6; T1Y 6; T1Z 6; T2 1 3 4 5 6; T3 6; T4 1 3 4 5 6; T5 1 3 4 5 6; T6 6; T7 6; T8 6; T9 6; T10 6; T11 6; T12 6; U1 1 6 11 12 13 18 19 23 24 25 38; U1AA H4 L4 L15 L16; U1B 3 4 22 23 24 25 29 30 33 34 36 37 42 43 44 45 53 54 60 61 62 63; U1LL 1 2 22; U1Q 4; U8FF 5; Y1B 1 2

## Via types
v1: diameter 0.356, hole 0.203, TOP to BOTTOM, 326 vias
v2: diameter 0.381, hole 0.203, L9_POWER_DVDD1 to BOTTOM, 837 vias
v3: diameter 0.406, hole 0.203, TOP to BOTTOM, 541 vias
v4: diameter 0.635, hole 0.305, TOP to BOTTOM, 162 vias
v5: diameter 0.508, hole 0.254, TOP to BOTTOM, 297 vias
v6: diameter 0.356, hole 0.203, TOP to L4_GROUND, 1109 vias
v7: diameter 0.457, hole 0.152, TOP to BOTTOM, 4 vias
v8: diameter 0.66, hole 0.406, TOP to BOTTOM, 72 vias
v9: diameter 0.66, hole 0.508, TOP to BOTTOM, 4 vias

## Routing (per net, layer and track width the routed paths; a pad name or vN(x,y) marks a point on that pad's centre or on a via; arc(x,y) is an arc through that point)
AVDD1: length 0.4
  BOTTOM w0.305: v1(153.81,171.95) 153.81,171.96 C8AA.1 ; C5AA.1 153.84,172.72 v1(153.81,172.75)
  vias: v1(153.01,173.55) v1(153.01,164.75) v1(153.81,173.55) v1(153.81,166.35) v1(153.81,165.55) v1(153.81,164.75) v1(154.61,173.55) v1(154.61,164.75) v5(165.99,177.62) v5(166.11,178.26) v5(166.49,177.12) v5(166.62,177.75) v5(167.13,177.24)
AVDD1_ADC:
  vias: v1(157.01,171.15) v1(157.01,167.15) v1(157.81,171.15) v1(157.81,167.15) v5(174.37,176.73) v5(174.75,177.64) v5(175.13,176.73) v5(175.51,177.75)
AVDD2: length 27.5
  TOP w0.508: E1.2 v5(190.93,216.82)
  L10_SIGNAL w0.254: v5(190.93,216.82) 192.28,215.47 192.28,208.1 192.02,207.85 192.02,199.09 190.24,197.31 189.35,197.31 186.94,194.9 186.31,194.9 v5(185.67,194.26)
  vias: v1(153.01,175.95) v1(153.01,172.75) v1(153.01,170.35) v1(153.01,167.95) v1(153.01,165.55) v1(153.01,162.35) v1(153.81,167.95) v5(186.05,193.75) v5(186.43,194.26) v5(186.81,193.75)
DVDD1: length 2.1
  TOP w0.508: v4(189.1,175.97) 189.49,176.37 E1M.2
  BOTTOM w0.305: v1(159.41,171.95) 159.23,171.77 C70AA.1
  vias: v1(158.61,170.35) v1(158.61,169.55) v1(158.61,168.75) v1(158.61,167.95) v1(158.61,167.15) v1(160.21,170.35) v1(160.21,169.55) v1(160.21,168.75) v1(160.21,167.95) v4(188.34,177.5) v4(188.34,176.73) v4(188.34,175.97) v4(189.1,177.5) v4(189.1,176.73) v4(189.23,175.34)
DVDD1P0_SNS: length 2.6
  TOP w0.305: U1M.13 188.34,185.5 188.97,184.87 R8M.2
DVDD1P0V_ADJ: length 1.5
  TOP w0.203: R4M.1 184.05,186.07 U1M.8
DVDD1P0V_EN: length 5.5
  TOP w0.254: R3M.1 190.24,189.05 188.76,187.57 U1M.16
  TOP w0.508: v5(189.09,189.69) 189.47,189.32 R3M.1
  BOTTOM w0.508: R2M.2 188.59,190.57 189.09,190.06 v5(189.09,189.69)
DVDD1P0V_REF: length 1.7
  TOP w0.203: U1M.5 184.69,187.57 C5M.1
DVDD1P0V_REG: length 1.5
  TOP w0.203: C4M.1 184.04,187.07 U1M.6
DVDD1P0V_SS: length 1.5
  TOP w0.254: C6M.1 189.42,186.57 U1M.14
GND_SIGNAL: length 218.2
  TOP w0.127: v1(156.21,163.15) 156.48,163.15 157.25,162.38 ; 157.22,175.9 156.33,175.01 155.98,175.01
  TOP w0.203: U8FF.7 168.72,116.5 v6(168.45,116.76) ; U7FF.6 v6(161.29,117.3) ; U5FF.8 168.41,122.05 v6(168.02,121.67) ; 170.43,146.89 170.24,147.09 U1FF.10 ; U2FF.8 168.41,138.56 168.02,138.18 v6(167.51,138.18) ; U2FF.7 166.77,139.47 166.51,139.21 v6(166.11,139.21) ; 160.28,156.2 160.04,156.44 T11.2 T11.5 157.53,156.44 ; U1LL.8 180.23,215.7 180.5,215.98 v3(180.5,216.23) ; T4.2 146.81,149.94 ; T1.2 128.14,150.06 ; U1LL.14 177.95,216.35 ; U3FF.8 168.41,131.69 v6(168.4,131.7) 167.91,131.21 U3FF.7 ; v6(168.91,131.7) 169.4,131.21 U3FF.10 ; U1X.PAD 177.72,182.56 U1X.7 ; 161.05,181.9 v6(160.88,181.9) T7.5 T7.2 157.97,181.9 157.62,182.26 ; U6FF.6 v6(153.67,117.17) ; T5.2 146.81,147.14 ; 183.33,186.56 183.33,186.57 U1M.7 186.59,186.57 U1M.PAD ; v6(168.91,141.48) 168.92,141.47 ; U3FF.2 167.91,133.71 v6(168.4,133.22) ; v6(168.91,133.22) 169.4,133.71 U3FF.15 ; U8FF.6 v6(169.54,117.09) ; T2.2 128.14,147.27
  TOP w0.241: v1(152.34,173.61) 152.34,172.81 v1(152.32,172.8)
  TOP w0.254: 160.45,161.72 160.45,162.1 160.21,162.35 v1(160.21,162.35) v1(159.41,163.15) v1(158.61,163.15) v1(157.81,162.35) 157.81,162.33 157.4,161.93 ; R4NN.2 164.6,184.44 164.74,184.58 ; 164.74,184.58 164.79,184.63 165.05,184.63 165.21,184.79 U1NN.7 ; 164.74,184.58 164.62,184.7 C4NN.2 C5NN.2 ; U1FF.7 167.33,147.09 167,146.76 ; v6(160.63,176.8) 160.63,176.37 v1(160.21,175.95) v1(159.41,175.15) v1(158.61,175.15) v1(157.81,175.95) 157.81,175.98 157.58,176.2 v6(157.58,176.71) ; U4FF.PAD 162.05,123.95 v6(162.05,123.44) 162.05,123.23 162.06,123.23 U4FF.8 ; 151,170.64 151.29,170.35 v1(152.21,170.35) v1(153.01,169.55) v1(153.01,168.75) v1(152.21,167.95) 151.36,167.95 151.13,167.72 ; R8LL.2 v4(170.38,218.26) ; 146.43,105.61 146.43,104.88 146.81,104.5 U10FF.6 ; v4(165.11,142.61) 165.14,142.63 165.44,142.63 165.68,142.39 166.22,142.39 166.64,141.97 U2FF.2 ; U1FF.PAD 168.4,148.08 168.4,147.36 168.41,147.36 U1FF.8 ; v3(181.45,226.38) 181.47,226.39 C14OO.2 ; U1FF.2 167.36,149.66 167.51,149.81 ; v3(165.15,154.29) 165.06,154.39 C1FF.1 ; C27B.2 148.71,107.01 148.84,106.88 v5(148.84,106.76) ; U1P.PAD 190.77,223.74 U1P.4
  TOP w0.305: R4X.2 177.8,180.29 ; 177.8,180.29 177.41,180.29 C4X.2 ; 177.8,180.29 177.81,180.3 177.81,181.21 U1X.7 ; v3(182.28,213.56) 182.27,213.57 C10LL.2 ; R16LL.2 v3(182.99,216.36) ; R9LL.2 182.14,210.65 v3(182.28,210.51) 183.03,210.51 R21LL.1 ; R18LL.2 v4(169.7,215.09) ; 183.33,186.56 182.7,186.56 182.07,187.2
  TOP w0.381: 177.7,216.1 v6(177.96,216.36)
  TOP w0.508: R12LL.2 171.74,212.17 v5(171.1,212.17) ; R13FF.2 164.2,121.48 v5(164.46,121.74) ; C12FF.1 150.11,113.67 v4(149.91,113.87) ; C10LL.2 183.28,213.94 C9LL.2 ; 177.7,216.1 v6(177.7,215.98) v6(177.7,215.47) ; C8NN.2 v4(173.44,185.74) ; v4(174.71,181.3) C10NN.2 ; v5(171.07,178.64) C6NN.2 ; R7FF.2 v4(167.52,129.85) ; 177.7,203.66 v5(177.7,204.42) v5(177.7,205.18) v5(177.7,205.82) v5(177.7,206.78) v5(177.7,207.54) U1LL.35 U1LL.36 U1LL.37 ; v4(149.73,101.83) 149.72,101.85 C19FF.2 ; v5(164.72,177.75) 164.47,178 C12N.2 ; C7NN.2 176.02,176.2 v6(176.2,176.02) ; v5(138.75,108.95) 138.75,108.62 139.09,108.28 139.09,108.06 RESET.2B ; v5(171.1,213.31) 171.74,213.31 R11LL.2 ; v4(192.28,180.16) 193.16,181.05 GND1.1 ; v6(178.84,175.97) 178.84,176.26 C9X.2 ; v4(190.12,184.44) 190.12,184.87 C6M.2 ; C10X.2 185.16,175.47 v5(185.16,175.34) ; R2LL.2 171.74,211.02 v5(171.1,211.02) ; GPIO.16 v4(174.5,107.82) ; C2FF.1 v6(170.94,144.35) ; v4(169.7,215.09) 170.47,215.09 171.1,215.72 C6LL.2 ; C9M.2 v5(187.95,174.33) ; v6(181.58,175.39) 181.9,175.39 C23X.2 ; AGC.13 v4(160.91,103.97) ; GPIO.14 v4(173.23,107.82) ; DS1P.C v5(144.78,230.58) ; R15FF.2 v6(170.55,121.53) ; C11FF.2 v4(167.27,126.88) ; C18FF.1 v4(143.9,101.9) 143.9,101.89 R34FF.2 ; GPIO.15 v4(174.5,102.11) ; GND0.1 191.92,230 TP2A.1 ; RESET.2A v5(133.7,108.51) ; AGC.14 v4(160.91,107.87) ; R4LL.2 171.86,214.58 171.61,214.32 v5(171.1,214.32) ; C17FF.2 v5(171.2,112.53) ; C8FF.1 v4(163.82,128.07) ; C9FF.1 v4(170.17,126.88) ; R21FF.2 v5(169.54,111.69) ; GND3.1 v4(122.3,104.9) ; AGC.16 v4(162.18,107.9) ; AGC.15 v4(162.18,103.97) ; R17FF.2 v6(154.13,112.27) ; 167.52,138.17 v6(167.51,138.18) ; DS100.C v5(144.78,231.85) ; C15FF.2 v6(154.81,112.09) ; C10FF.2 v4(160.92,126.79)
  TOP w0.762: v4(182.88,189.18) 182.91,189.15 C5M.2 ; v4(181.99,185.88) 182.04,185.93 R4M.2 ; C4M.2 182.07,187.2 v4(181.99,187.28) ; C7LL.2 v4(186.09,218.52)
  BOTTOM w0.203: v5(146.56,217.37) v5(145.41,218.52) 144.31,219.62 U1.21 144.31,221.59 C6.2 ; v1(162.61,175.15) 162.4,174.95 C72AA.2 ; 154.43,156.8 154.81,157.05 T8.2 T8.5 157.22,157.05 ; v4(150.62,116.28) 151,116.28 151.35,116.63 U1B.35 ; C71AA.2 162.45,163.3 v1(162.61,163.15) ; 146.76,165.51 147.62,165.51 v2(147.97,165.38) T6.2 v2(148.49,164.64) T6.5 v2(149.05,163.73) 148.79,162.97 ; R11AA.2 163.32,155.66 163.32,156.34 ; 148.66,176.02 148.66,175.13 v2(148.87,174.65) T3.2 T3.5 147.29,172.52 146.63,172.34 ; 157.22,181.31 156.87,180.95 T12.2 T12.5 154.2,180.95 154.18,180.93 ; C13.2 143.33,207.9 v5(143.89,207.34) ; 147.31,216.62 U1.37
  BOTTOM w0.254: v5(146.56,217.37) 146.81,217.13 ; v5(146.56,217.37) v5(145.31,216.13) U1.8 v2(145.31,213.69) 145.31,213.1 C7.2 ; v5(146.56,217.37) v5(147.81,218.62) ; 146.81,217.13 U1.5 146.81,213.12 C5.2 146.87,212.22 C1.2 ; 146.81,217.13 v5(147.83,216.1) 148.81,215.13 U1.40 150.65,215.13 C4.2 ; v2(142.11,212.17) 142.22,212.06 U3.C2 ; 163.32,156.34 163.5,156.16 v2(164.01,156.16) ; 141.83,219.09 141.96,218.96 C9.2 ; 141.83,219.09 v2(141.77,219.15) 141.73,219.15 ; 141.83,219.09 141.83,218.96 ; C8.2 v2(142.75,213.06) ; v5(147.81,218.62) 148.31,219.13 U1.29 ; v5(147.81,218.62) U1.33
  BOTTOM w0.279: R2AA.2 v1(153.81,171.15)
  BOTTOM w0.305: P1K.F24 v2(186.78,130.27) ; U1Q.6 187.36,203.15 U1Q.PAD 187.86,203.15 U1Q.3 ; P1K.B14 v2(189.32,142.97) ; P1K.C8 v2(189.32,148.05) ; v2(186.78,154.4) P1K.D3 ; U1K.4 174.97,101.64 v4(174.5,102.11) ; v1(158.61,171.15) 158.62,171.15 C70AA.2 ; P1K.J20 v2(180.43,132.81) ; R7Q.2 v2(187.36,197.49) ; v1(152.21,165.55) C13AA.2 ; P1K.G20 v2(182.97,132.81)
  BOTTOM w0.381: C1K.2 169.23,102.94 v2(169.93,102.94) U1K.7
  BOTTOM w0.508: Y2B.2 164.54,127.36 v4(163.82,128.07) ; C40LL.2 170.34,215.72 v4(169.7,215.09) ; C41B.2 154.61,105.16 v2(154.61,104.67) R5B.2 ; v5(190.75,201.37) 190.79,201.34 190.79,200.62 190.79,200.62 Q1Q.2 ; TP17K.1 184.12,234.81 C2A.2 ; C22B.1 v4(145.22,120.8) ; C2LL.2 171.24,210.89 v5(171.1,211.02) ; v3(190.57,223.76) 190.95,224.14 C5P.2 ; Y1B.3 v2(158.26,112.33) ; C26B.2 v2(141.98,105.15) ; C28B.2 v4(152.33,104.64) ; C21B.1 v5(138.08,117.59) ; C23B.1 v4(146.74,120.8) ; R1K.2 v2(177.54,104.66)
  vias: v1(152.21,175.95) v1(152.21,164.75) v1(152.21,162.35) v1(153.01,175.15) v1(153.01,174.35) v1(153.01,171.95) v1(153.01,171.15) v1(153.01,167.15) v1(153.01,166.35) v1(153.01,163.95) v1(153.01,163.15) v1(153.81,167.15) v1(153.81,163.15) v1(153.81,162.35) v1(154.61,175.95) v1(154.61,175.15) v1(154.61,172.75) v1(154.61,171.95) v1(154.61,171.15) v1(154.61,167.15) v1(154.61,166.35) v1(154.61,165.55) v1(154.61,163.15) v1(154.61,162.35) v1(155.41,175.15) v1(155.41,174.35) v1(155.41,173.55) v1(155.41,171.15) v1(155.41,170.35) v1(155.41,167.95) v1(155.41,167.15) v1(155.41,164.75) v1(155.41,163.95) v1(155.41,163.15) v1(156.21,175.15) v1(156.21,174.35) v1(156.21,172.75) v1(156.21,171.95) v1(156.21,170.35) v1(156.21,167.95) v1(156.21,166.35) v1(156.21,165.55) v1(156.21,163.95) v1(157.01,175.95) v1(157.01,174.35) v1(157.01,171.95) v1(157.01,170.35) v1(157.01,167.95) v1(157.01,166.35) v1(157.01,163.95) v1(157.01,162.35) v1(157.81,174.35) v1(157.81,171.95) v1(157.81,170.35) v1(157.81,169.55) v1(157.81,168.75) v1(157.81,167.95) v1(157.81,166.35) v1(157.81,163.95) v1(158.61,173.55) v1(158.61,164.75) v1(159.41,170.35) v1(159.41,169.55) v1(159.41,168.75) v1(159.41,167.95) v1(159.41,167.15) v1(159.41,166.35) v1(160.21,174.35) v1(160.21,163.95) v1(161.01,170.35) v1(161.01,169.55) v1(161.01,168.75) v1(161.01,167.95) v1(162.61,173.55) v1(162.61,171.95) v1(162.61,170.35) v1(162.61,169.55) v1(162.61,168.75) v1(162.61,167.95) v1(162.61,166.35) v1(162.61,164.75) v1(163.41,175.15) v1(163.41,173.55) v1(163.41,171.95) v1(163.41,170.35) v1(163.41,169.55) v1(163.41,166.35) v1(163.41,164.75) v1(163.41,163.15) v1(165.01,169.55) v1(165.01,168.75) v1(167.44,113.9) v1(177.52,214.53) v1(177.52,214.12) v1(177.52,213.72) v1(177.52,213.31) v1(177.52,212.9) v1(177.52,212.5) v1(177.52,212.09) v1(177.52,211.69) v1(177.52,211.28) v1(177.52,210.87) v1(177.52,210.47) v1(177.52,210.06) v1(177.52,209.65) v1(177.52,209.25) v1(177.52,208.84) v1(177.52,208.43) v1(177.87,214.53) v1(177.87,214.12) v1(177.87,213.72) v1(177.87,213.31) v1(177.87,212.9) v1(177.87,212.5) v1(177.87,212.09) v1(177.87,211.69) v1(177.87,211.28) v1(177.87,210.87) v1(177.87,210.47) v1(177.87,210.06) v1(177.87,209.65) v1(177.87,209.25) v1(177.87,208.84) v1(177.87,208.43) v2(124.25,185.02) v2(124.41,183.21) v2(124.46,156.8) v2(124.58,211.74) v2(124.58,154.89) v2(124.53,128.2) v2(124.51,126.57) v2(124.66,210.06) v2(124.97,185.02) v2(125.04,126.52) v2(125.19,183.21) v2(125.14,156.72) v2(125.22,128.27) v2(125.5,211.76) v2(125.52,210.01) v2(125.6,184.91) v2(125.6,126.44) v2(125.73,183.21) v2(125.75,128.5) v2(125.8,156.62) v2(125.8,154.94) v2(126.19,211.94) v2(126.24,209.78) v2(126.26,184.81) v2(126.24,183.14) v2(126.36,128.75) v2(126.44,156.62) v2(126.44,154.94) v2(126.49,126.42) v2(126.78,182.98) v2(127.02,211.94) v2(127,184.74) v2(127.07,156.62) v2(127.07,154.94) v2(127,129.39) v2(127.12,209.78) v2(127.2,126.9) v2(127.46,182.84) v2(127.48,130.05) v2(127.76,184.61) v2(127.71,156.62) v2(127.71,154.94) v2(127.79,127.43) v2(128.09,211.91) v2(128.01,209.73) v2(128.09,130.63) v2(128.11,182.67) v2(128.39,184.48) v2(128.34,156.62) v2(128.34,154.94) v2(128.32,127.89) v2(128.57,131.14) v2(128.83,209.73) v2(128.81,182.5) v2(128.88,128.45) v2(128.98,156.62) v2(128.98,154.94) v2(129.16,184.23) v2(129.16,131.7) v2(129.33,211.76) v2(129.34,182.36) v2(129.46,209.53) v2(129.41,128.93) v2(129.61,156.62) v2(129.61,154.94) v2(129.79,184.1) v2(129.79,132.31) v2(129.94,182.2) v2(129.94,129.52) v2(130.15,209.22) v2(130.22,211.48) v2(130.25,156.62) v2(130.25,154.94) v2(130.4,133.02) v2(130.55,183.97) v2(130.54,182.01) v2(130.53,130.08) v2(130.76,208.92) v2(130.88,156.62) v2(130.88,154.94) v2(131.09,211.15) v2(131.19,183.85) v2(131.14,181.82) v2(131.11,133.76) v2(131.19,130.68) v2(131.44,208.46) v2(131.52,156.62) v2(131.52,154.94) v2(131.67,131.24) v2(131.75,134.37) v2(131.82,183.59) v2(131.81,181.57) v2(131.9,210.72) v2(132.05,207.95) v2(132.15,156.62) v2(132.15,154.94) v2(132.2,131.78) v2(132.46,183.34) v2(132.48,181.33) v2(132.59,210.31) v2(132.56,135.1) v2(132.64,207.39) v2(132.79,156.62) v2(132.79,154.94) v2(132.79,132.34) v2(133.09,183.08) v2(133.02,135.64) v2(133.3,209.75) v2(133.25,206.81) v2(133.2,181.06) v2(133.42,156.62) v2(133.42,154.94) v2(133.42,132.77) v2(133.73,182.83) v2(133.73,136.3) v2(133.78,133.43) v2(133.86,206.1) v2(134.01,209.09) v2(134.02,180.7) v2(134.06,156.62) v2(134.06,154.94) v2(134.34,136.78) v2(134.47,205.46) v2(134.49,182.58) v2(134.41,133.96) v2(134.62,208.46) v2(134.64,156.62) v2(134.69,154.94) v2(134.79,180.35) v2(134.96,137.5) v2(134.97,134.49) v2(135.1,204.83) v2(135.1,182.3) v2(135.23,207.82) v2(135.28,156.62) v2(135.45,180.02) v2(135.41,154.94) v2(135.48,138.03) v2(135.61,135.05) v2(135.76,207.27) v2(135.79,204.17) v2(135.8,181.98) v2(135.89,156.64) v2(136.05,179.76) v2(136.09,154.94) v2(136.09,138.63) v2(136.18,110.06) v2(136.24,135.79) v2(136.37,206.63) v2(136.49,181.63) v2(136.47,156.75) v2(136.62,203.38) v2(136.64,179.44) v2(136.66,107.34) v2(136.78,155.02) v2(136.75,139.14) v2(136.85,136.37) v2(137.18,205.84) v2(137.11,181.34) v2(137.18,179.15) v2(137.21,157.1) v2(137.34,155.2) v2(137.36,139.73) v2(137.59,202.64) v2(137.65,181.02) v2(137.62,137.01) v2(137.82,205.31) v2(137.84,178.76) v2(137.82,157.51) v2(137.87,155.45) v2(137.89,137.53) v2(137.89,109.97) v2(137.97,140.21) v2(138.06,108.38) v2(138.12,106.71) v2(138.21,180.68) v2(138.3,202.13) v2(138.33,157.89) v2(138.43,178.39) v2(138.45,155.86) v2(138.45,138) v2(138.61,204.67) v2(138.85,180.3) v2(138.86,158.27) v2(138.86,140.69) v2(138.91,138.37) v2(139.05,178.02) v2(139.04,156.26) v2(139.16,201.6) v2(139.34,158.62) v2(139.44,179.91) v2(139.56,177.71) v2(139.7,203.99) v2(139.62,156.69) v2(139.67,141.12) v2(139.7,138.79) v2(139.85,158.98) v2(140.08,179.53) v2(140.05,177.37) v2(140.21,157.1) v2(140.31,200.99) v2(140.33,159.29) v2(140.41,141.43) v2(140.43,139.12) v2(140.69,203.43) v2(140.61,176.96) v2(140.73,179.12) v2(140.76,157.48) v2(140.84,159.64) v2(141.02,141.63) v2(141.17,176.54) v2(141.17,139.4) v2(141.32,178.73) v2(141.35,160.02) v2(141.3,157.91) v2(141.65,200.74) v2(141.7,203.05) v2(141.75,176.1) v2(141.7,141.73) v2(141.73,139.58) v2(141.96,178.3) v2(141.93,160.43) v2(141.91,158.35) v2(142.24,175.85) v2(142.21,107.24) v2(142.39,177.99) v2(142.49,160.83) v2(142.47,158.75) v2(142.62,202.74) v2(142.62,200.51) v2(142.76,139.77) v2(142.87,175.46) v2(142.83,141.85) v2(142.97,177.55) v2(143.03,161.19) v2(143.05,159.18) v2(143.38,174.96) v2(143.33,106.81) v2(143.41,139.83) v2(143.56,202.54) v2(143.53,177.11) v2(143.53,161.55) v2(143.56,159.54) v2(143.51,141.91) v2(143.63,200.36) v2(143.77,134.44) v2(144.02,161.98) v2(144.14,165.56) v2(144.12,159.95) v2(144.12,139.83) v2(144.27,176.61) v2(144.27,174.58) v2(144.45,164.44) v2(144.45,106.55) v2(144.55,162.33) v2(144.68,200.18) v2(144.78,202.31) v2(144.78,176.23) v2(144.78,173.43) v2(144.7,160.38) v2(144.85,139.83) v2(144.9,166.19) v2(144.96,141.91) v2(145.03,164.77) v2(145.03,163.55) v2(145.08,162.74) v2(145.29,175.85) v2(145.24,160.78) v2(145.54,172.92) v2(145.57,163.04) v2(145.51,139.83) v2(145.64,163.93) v2(145.74,200.1) v2(145.77,165.08) v2(145.77,141.9) v2(145.9,202.26) v2(145.82,161.19) v2(146.05,176.25) v2(146.3,172.42) v2(146.35,139.85) v2(146.48,179.53) v2(146.4,161.62) v2(146.45,141.92) v2(146.56,177.07) v2(146.56,167.34) v2(146.5,164.04) v2(146.91,200.05) v2(146.96,175.31) v2(146.94,161.24) v2(147.09,202.21) v2(147.06,177.93) v2(147.06,171.91) v2(147.06,166.6) v2(147.01,139.85) v2(147.1,141.9) v2(147.32,167.84) v2(147.39,165.97) v2(147.69,176.35) v2(147.65,172.95) v2(147.69,133.85) v2(147.7,177.75) v2(147.83,171.4) v2(147.85,141.91) v2(147.85,139.85) v2(147.95,168.35) v2(147.95,161.62) v2(148.03,199.87) v2(148.18,173.66) v2(148.26,202.06) v2(148.33,177.5) v2(148.59,170.89) v2(148.64,141.91) v2(148.64,139.85) v2(148.71,168.86) v2(148.84,162.38) v2(148.94,199.59) v2(149.1,176.99) v2(149.07,175.31) v2(149.22,201.78) v2(149.35,170.38) v2(149.48,175.9) v2(149.43,141.94) v2(149.63,139.88) v2(149.73,162.89) v2(149.81,199.19) v2(149.96,201.53) v2(149.98,176.48) v2(150.24,141.94) v2(150.49,163.4) v2(150.44,139.88) v2(150.62,175.97) v2(150.85,198.55) v2(151.03,141.96) v2(151.18,200.92) v2(151.13,163.91) v2(151.38,175.46) v2(151.41,139.93) v2(151.56,197.94) v2(151.71,142.11) v2(151.94,200.41) v2(152.02,175.34) v2(152.02,163.91) v2(152.27,197.08) v2(152.27,140.11) v2(152.4,174.83) v2(152.4,158.57) v2(152.4,157.18) v2(152.4,155.91) v2(152.4,154.89) v2(152.45,142.44) v2(152.6,199.85) v2(152.91,159.34) v2(152.96,142.73) v2(153.01,196.19) v2(153.03,153.49) v2(153.03,140.41) v2(153.02,123.22) v2(153.02,122.07) v2(153.02,120.93) v2(153.41,199.16) v2(153.44,195.33) v2(153.77,194.51) v2(153.9,183.19) v2(153.9,155.11) v2(153.82,143.46) v2(153.87,140.9) v2(153.95,183.87) v2(153.97,182.48) v2(153.97,181.59) v2(153.95,153.85) v2(153.95,153.09) v2(154.02,193.68) v2(154.02,179.94) v2(154,179.15) v2(154.13,198.27) v2(154.15,192.66) v2(154.1,180.72) v2(154.18,160.22) v2(154.28,184.43) v2(154.23,178.23) v2(154.28,144.17) v2(154.3,191.77) v2(154.33,190.76) v2(154.3,189.82) v2(154.33,188.88) v2(154.3,187.94) v2(154.33,186.92) v2(154.33,186.16) v2(154.33,185.27) v2(154.3,177.24) v2(154.3,160.86) v2(154.43,161.75) v2(154.73,197.36) v2(154.73,144.98) v2(154.79,141.45) v2(154.84,135.54) v2(155.17,155.11) v2(155.12,153.87) v2(155.19,145.62) v2(155.22,196.55) v2(155.37,146.66) v2(155.4,142.11) v2(155.57,151.72) v2(155.57,150.95) v2(155.57,148.87) v2(155.55,147.78) v2(155.65,195.56) v2(155.6,150.04) v2(155.98,194.51) v2(155.95,142.7) v2(156.03,189.87) v2(156.03,188.93) v2(156.03,187.99) v2(156.08,187.1) v2(156.08,186.36) v2(156.08,185.62) v2(156.08,184.84) v2(156.13,193.68) v2(156.13,116.7) v2(156.13,115.3) v2(156.13,112.13) v2(156.13,110.98) v2(156.13,108.7) v2(156.13,107.55) v2(156.26,192.74) v2(156.26,191.8) v2(156.26,190.78) v2(156.23,184.23) v2(156.36,143.31) v2(156.46,182.93) v2(156.6,139.04) v2(156.74,140.2) v2(156.79,134.47) v2(156.8,137.34) v2(156.92,184.86) v2(156.92,184.15) v2(156.97,144.35) v2(157.38,145.34) v2(157.48,178.13) v2(157.48,177.24) v2(157.48,161.49) v2(157.4,153.14) v2(157.48,151.51) v2(157.58,150.67) v2(157.58,147.52) v2(157.53,146.28) v2(157.66,181.36) v2(157.6,160.73) v2(157.6,150.06) v2(157.6,149.3) v2(157.6,148.41) v2(157.6,146.89) v2(157.78,184.89) v2(157.78,184.18) v2(157.73,182.93) v2(157.83,159.92) v2(157.86,157.18) v2(157.86,156.16) v2(157.86,154) v2(157.96,159.11) v2(157.91,158.17) v2(157.99,155.02) v2(158.39,137.38) v2(158.6,181.87) v2(158.6,181.18) v2(158.51,140.11) v2(158.6,139.02) v2(158.62,183.8) v2(158.62,182.86) v2(158.93,180.09) v2(158.93,179.07) v2(163.09,142.9) v2(164.54,148.69) v2(165.05,162.03) v2(165.3,154.54) v2(165.81,152.45) v2(165.83,142.7) v2(165.81,141.89) v2(165.83,140.36) v2(166.06,138.53) v2(166.32,156.8) v2(166.55,162.69) v2(166.95,170.08) v2(167.18,162.03) v2(167.33,159.89) v2(167.33,158.32) v2(167.33,156.92) v2(167.43,136.3) v2(167.44,116.19) v2(167.44,115.05) v2(168.12,138.66) v2(169.09,169.39) v2(169.16,168.4) v2(169.21,167.57) v2(169.37,173.26) v2(169.7,177.01) v2(170.66,168) v2(170.61,166.55) v2(170.79,132.89) v2(171.32,119.84) v2(171.47,166.52) v2(171.42,131.4) v2(171.7,172.06) v2(171.73,165.08) v2(171.83,174.7) v2(171.96,139.83) v2(172.57,146.15) v2(173.1,142.01) v2(173.2,138.56) v2(173.28,132.82) v2(173.4,173.84) v2(173.43,128.53) v2(173.43,122.43) v2(173.48,116.97) v2(173.76,170.05) v2(174.37,140.41) v2(174.6,173.03) v2(174.72,175.41) v2(174.93,149.3) v2(174.9,146.74) v2(174.95,144.3) v2(175,167.62) v2(175.08,139.96) v2(175.44,129.11) v2(175.56,174.93) v2(175.54,172.75) v2(175.51,127.66) v2(175.51,126.52) v2(175.51,123.01) v2(175.56,118.72) v2(175.69,171.81) v2(175.84,142.34) v2(175.87,139.04) v2(175.94,117.38) v2(176.68,174.7) v2(176.78,169.72) v2(176.83,150.73) v2(177.09,166.7) v2(177.09,165.23) v2(177.04,163.45) v2(177.06,160.66) v2(177.09,133) v2(177.04,120.3) v2(177.11,145.72) v2(177.21,148.01) v2(177.24,137.67) v2(177.24,130.71) v2(177.77,118.57) v2(177.95,172.62) v2(177.92,129.11) v2(178.08,142.22) v2(178.38,174.68) v2(178.66,121.92) v2(178.86,155.67) v2(179.14,133) v2(179.3,145.47) v2(179.27,142.95) v2(179.3,141.84) v2(179.32,150.5) v2(180.06,174.65) v2(180.11,172.62) v2(180.39,109.83) v2(180.43,156.94) v2(180.43,155.67) v2(180.43,151.86) v2(180.43,148.05) v2(180.43,144.24) v2(180.43,140.43) v2(180.43,136.62) v2(180.43,129) v2(180.43,125.19) v2(180.43,121.38) v2(180.41,117.68) v2(180.43,113.76) v2(181.35,174.68) v2(181.7,158.21) v2(181.7,156.94) v2(181.7,154.4) v2(181.7,153.13) v2(181.7,149.32) v2(181.7,145.51) v2(181.7,141.7) v2(181.7,137.89) v2(181.7,130.27) v2(181.7,126.46) v2(181.7,122.65) v2(181.7,118.84) v2(181.71,114.91) v2(181.7,111.22) v2(181.7,108.68) v2(182.09,172.59) v2(182.85,174.65) v2(182.97,156.94) v2(182.97,155.67) v2(182.97,151.86) v2(182.97,148.05) v2(182.97,144.24) v2(182.97,140.43) v2(182.97,136.62) v2(182.97,129) v2(182.97,125.19) v2(182.97,121.38) v2(182.98,117.68) v2(182.97,113.76) v2(182.93,109.83) v2(184.02,172.57) v2(184.24,158.21) v2(184.24,154.4) v2(184.24,153.13) v2(184.24,149.32) v2(184.24,145.51) v2(184.24,141.7) v2(184.24,137.89) v2(184.24,130.27) v2(184.24,126.46) v2(184.24,122.65) v2(184.24,118.84) v2(184.25,114.91) v2(184.24,111.22) v2(184.24,108.68) v2(184.33,174.68) v2(184.88,138.52) v2(185.06,172.52) v2(185.51,156.94) v2(185.51,155.67) v2(185.51,151.86) v2(185.51,148.05) v2(185.51,144.24) v2(185.51,140.43) v2(185.51,136.62) v2(185.51,132.81) v2(185.51,125.19) v2(185.51,121.38) v2(185.52,117.65) v2(185.51,113.76) v2(185.52,109.83) v2(185.62,174.58) v2(186.08,172.16) v2(186.78,158.21) v2(186.78,153.13) v2(186.78,149.32) v2(186.78,145.51) v2(186.78,141.7) v2(186.78,137.89) v2(186.78,134.08) v2(186.78,126.46) v2(186.78,122.65) v2(186.78,118.84) v2(186.79,114.91) v2(186.78,111.22) v2(186.78,108.68) v2(186.97,174.04) v2(187.12,171.27) v2(187.73,170.08) v2(187.7,162.41) v2(187.88,168.78) v2(187.88,163.5) v2(187.91,167.21) v2(187.91,166.04) v2(187.91,164.54) v2(188.05,156.94) v2(188.05,151.86) v2(188.05,150.59) v2(188.05,146.78) v2(188.05,142.97) v2(188.05,139.16) v2(188.05,135.35) v2(188.05,131.54) v2(188.05,127.73) v2(188.05,123.92) v2(188.05,112.49) v2(188.03,109.83) v2(188.11,173.28) v2(188.97,172.26) v2(189.32,158.21) v2(189.32,154.4) v2(189.32,153.13) v2(189.32,144.24) v2(189.32,139.16) v2(189.32,137.89) v2(189.32,134.08) v2(189.32,132.81) v2(189.32,129) v2(189.32,127.73) v2(189.32,123.92) v2(189.32,122.65) v2(189.32,118.84) v2(189.32,117.57) v2(189.32,113.76) v2(189.32,111.22) v2(189.32,108.68) v2(189.63,171.05) v2(189.91,169.7) v2(189.99,168.3) v2(189.99,167.03) v2(189.99,164.52) v2(189.99,163.43) v2(190.02,165.71) v2(190.09,161.75) v2(190.59,158.21) v2(190.59,156.94) v2(190.59,155.67) v2(190.59,151.86) v2(190.59,150.59) v2(190.59,146.78) v2(190.59,145.51) v2(190.59,140.43) v2(190.59,136.62) v2(190.59,135.35) v2(190.59,131.54) v2(190.59,130.27) v2(190.59,126.46) v2(190.59,125.19) v2(190.59,121.38) v2(190.59,120.11) v2(190.59,116.3) v2(190.59,111.22) v2(190.62,114.89) v2(190.6,109.83) v2(191.86,158.21) v2(191.86,154.4) v2(191.86,153.13) v2(191.86,149.32) v2(191.86,148.05) v2(191.86,144.24) v2(191.86,142.97) v2(191.86,139.16) v2(191.86,137.89) v2(191.86,134.08) v2(191.86,132.81) v2(191.86,129) v2(191.86,127.73) v2(191.86,123.92) v2(191.86,122.65) v2(191.86,118.84) v2(191.86,117.57) v2(191.86,113.76) v2(191.86,112.49) v2(191.86,108.68) v3(119.89,162.38) v3(121.92,218.01) v3(121.92,133.55) v3(123.19,204.42) v3(123.7,190.2) v3(123.82,161.88) v3(124.33,216.1) v3(124.58,174.32) v3(124.71,134.82) v3(125.73,221.69) v3(125.73,214.07) v3(125.73,160.35) v3(125.85,188.04) v3(125.85,118.7) v3(125.98,131.01) v3(126.11,194.39) v3(126.24,171.27) v3(126.24,166.7) v3(126.36,191.72) v3(126.36,157.81) v3(126.36,111.2) v3(126.49,225.88) v3(126.49,217.76) v3(126.62,163.91) v3(126.74,137.75) v3(126.74,108.66) v3(127.38,123.39) v3(127.51,201.63) v3(127.63,180.54) v3(127.63,174.07) v3(127.89,204.93) v3(128.01,161.75) v3(128.27,166.83) v3(128.39,134.44) v3(128.52,164.92) v3(128.78,171.02) v3(128.9,190.7) v3(128.9,159.21) v3(129.03,110.44) v3(129.28,137.49) v3(129.41,187.66) v3(129.66,173.05) v3(129.66,128.09) v3(130.05,160.86) v3(130.3,166.7) v3(130.3,112.73) v3(130.43,194.26) v3(130.55,199.34) v3(130.68,140.03) v3(130.81,157.68) v3(130.93,114.89) v3(131.06,172.8) v3(131.19,188.93) v3(131.19,180.54) v3(131.32,119.58) v3(131.44,164.16) v3(131.44,161.88) v3(131.7,117.43) v3(131.82,110.19) v3(131.95,160.22) v3(131.95,122.76) v3(132.08,104.6) v3(132.71,232.23) v3(132.71,153.75) v3(132.84,224.49) v3(132.84,191.47) v3(132.84,137.49) v3(133.09,174.32) v3(133.09,119.33) v3(133.22,126.44) v3(133.73,140.29) v3(133.98,234.01) v3(134.11,221.95) v3(134.11,219.53) v3(134.24,217.63) v3(134.36,110.95) v3(134.49,213.44) v3(134.62,196.29) v3(134.62,187.91) v3(134.62,143.08) v3(135,116.41) v3(135.38,113.87) v3(135.51,153.75) v3(135.63,158.7) v3(135.76,198.2) v3(135.76,162.64) v3(135.89,234.01) v3(136.14,140.79) v3(136.27,145.75) v3(136.65,222.07) v3(136.78,216.1) v3(137.03,233.63) v3(137.16,158.57) v3(137.16,143.84) v3(137.28,173.05) v3(137.28,153.75) v3(137.54,210.26) v3(137.79,234.01) v3(138.05,165.81) v3(138.05,163.78) v3(138.43,219.79) v3(138.55,223.47) v3(138.55,214.58) v3(139.19,194.13) v3(139.19,161.24) v3(139.19,154.64) v3(139.19,132.28) v3(139.32,180.8) v3(139.44,210.52) v3(139.44,199.98) v3(139.44,172.29) v3(139.49,121.91) v3(139.7,234.01) v3(140.08,163.53) v3(140.21,174.45) v3(140.21,142.95) v3(140.33,133.68) v3(140.46,145.49) v3(140.59,166.83) v3(140.59,160.86) v3(140.84,151.21) v3(140.84,115.27) v3(140.97,207.34) v3(140.97,196.93) v3(140.97,189.94) v3(141.35,157.05) v3(141.6,234.01) v3(141.73,162.26) v3(141.73,126.19) v3(141.72,121.52) v3(141.86,165.05) v3(141.82,148.23) v3(142.11,166.83) v3(142.36,223.98) v3(142.36,143.59) v3(142.62,191.47) v3(142.87,172.29) v3(143,126.19) v3(143.13,186.77) v3(143.25,119.2) v3(143.38,180.16) v3(143.38,147.65) v3(143.51,234.01) v3(143.76,163.15) v3(143.76,104.47) v3(143.94,170.41) v3(143.94,167.93) v3(144.02,119.2) v3(144.14,153.87) v3(144.65,172.42) v3(144.78,189.56) v3(144.78,145.49) v3(144.9,196.04) v3(145.15,169.86) v3(145.15,169.41) v3(145.15,168.95) v3(145.15,168.49) v3(145.16,104.47) v3(145.41,234.01) v3(145.67,145.49) v3(145.92,186.77) v3(145.92,156.16) v3(146.05,155.02) v3(146.3,191.97) v3(146.37,169.17) v3(146.68,235.28) v3(146.81,122.12) v3(147.06,153.62) v3(147.17,122.84) v3(147.22,121.39) v3(147.57,236.3) v3(147.57,223.85) v3(148.08,182.45) v3(148.21,234.27) v3(148.59,237.19) v3(148.77,122.86) v3(148.71,121.36) v3(148.84,118.44) v3(149.1,184.23) v3(149.22,122.12) v3(149.35,119.33) v3(149.48,124.03) v3(149.98,149.43) v3(149.98,145.24) v3(150.49,237.19) v3(150.42,124.72) v3(150.62,236.17) v3(150.8,126.34) v3(150.87,101.3) v3(151,148.79) v3(151.13,154) v3(151.25,182.58) v3(151.76,233.63) v3(152.14,179.02) v3(152.27,181.43) v3(152.27,157.81) v3(152.27,154.13) v3(152.4,237.19) v3(152.36,135.5) v3(152.91,183.59) v3(153.67,126.32) v3(153.79,159.84) v3(154.05,151.08) v3(154.3,237.19) v3(154.3,223.47) v3(154.3,119.84) v3(154.56,146.25) v3(154.68,148.92) v3(154.84,153.24) v3(154.85,120.91) v3(154.94,125.05) v3(155.06,233.5) v3(155.95,127.46) v3(156.08,136.73) v3(156.08,125.23) v3(156.21,237.19) v3(156.33,104.85) v3(156.59,119.08) v3(156.97,220.93) v3(157.22,127.33) v3(158.11,237.19) v3(158.24,120.78) v3(158.37,123.39) v3(158.87,124.92) v3(159,221.06) v3(159,118.19) v3(160.02,237.19) v3(160.02,143.59) v3(160.02,142.19) v3(160.65,196.67) v3(160.78,119.08) v3(161.29,142.7) v3(161.8,157.41) v3(161.8,153.62) v3(161.92,237.19) v3(162.68,187.53) v3(162.81,118.95) v3(163.83,237.19) v3(163.83,138.76) v3(164.08,152.22) v3(164.01,150.09) v3(164.56,143.82) v3(165.73,237.19) v3(165.86,150.19) v3(166.88,156.41) v3(167.51,118.7) v3(167.64,237.19) v3(167.93,185.51) v3(167.93,185) v3(167.93,184.49) v3(168.44,185.51) v3(168.44,185) v3(168.44,184.49) v3(168.53,119.17) v3(168.95,185.51) v3(168.95,185) v3(168.95,184.49) v3(169.42,122.12) v3(169.54,237.19) v3(169.67,177.12) v3(169.83,227.66) v3(170.43,195.02) v3(170.69,177.12) v3(171.32,122.76) v3(171.45,237.19) v3(171.7,177.5) v3(171.96,183.72) v3(172.72,181.94) v3(172.72,180.67) v3(172.84,190.96) v3(172.84,189.69) v3(172.84,176.73) v3(172.97,191.72) v3(173.1,183.72) v3(173.23,177.88) v3(173.35,237.19) v3(173.35,179.53) v3(173.61,190.07) v3(173.99,191.47) v3(173.99,190.83) v3(175,191.47) v3(175,190.83) v3(175.26,237.19) v3(175.77,186.01) v3(176.02,191.47) v3(176.02,190.83) v3(176.78,178.89) v3(176.97,183.35) v3(176.97,182.34) v3(177.16,237.19) v3(177.48,183.35) v3(177.48,182.85) v3(177.48,182.34) v3(177.67,177.12) v3(177.99,183.35) v3(177.99,182.85) v3(177.99,182.34) v3(179.07,237.19) v3(180.44,227.9) v3(180.44,227.39) v3(180.44,226.88) v3(180.44,226.38) v3(180.44,225.87) v3(180.97,237.19) v3(180.94,227.9) v3(180.94,227.39) v3(180.94,226.88) v3(180.94,226.38) v3(180.94,225.87) v3(181.45,227.9) v3(181.45,227.39) v3(181.45,226.88) v3(181.45,225.87) v3(186.32,187.29) v3(186.32,186.78) v3(186.32,186.27) v3(186.83,187.29) v3(186.83,186.78) v3(186.83,186.27) v3(187.14,204.3) v3(187.14,203.8) v3(187.14,203.29) v3(187.33,187.29) v3(187.33,186.78) v3(187.33,186.27) v3(187.65,204.3) v3(187.65,203.8) v3(187.64,203.28) v3(187.99,212.29) v3(188.14,204.32) v3(188.14,203.78) v3(188.16,203.29) v3(188.59,236.68) v3(189.46,231.86) v3(189.55,223.76) v3(189.55,223) v3(189.55,222.24) v3(190.06,223.76) v3(190.06,223) v3(190.06,222.24) v3(190.57,223) v3(190.57,222.24) v3(191.39,236.68) v3(193.55,236.55) v3(193.67,196.8) v3(194.31,228.93) v3(194.31,227.03) v3(194.31,225.12) v3(194.31,214.33) v3(194.31,212.42) v3(194.31,210.52) v3(194.31,208.61) v3(194.31,206.71) v3(194.31,204.8) v3(194.31,202.9) v3(194.31,200.99) v3(194.31,199.09) v3(194.31,197.18) v3(194.31,195.28) v3(194.31,193.37) v3(194.31,191.47) v3(194.31,189.56) v3(194.31,186.89) v3(194.31,185.37) v3(194.31,183.72) v4(122.55,232.41) v4(138.61,121.61) v4(144.6,115.39) v4(144.68,110.11) v4(144.93,170.37) v4(144.94,167.96) v4(145.29,114.71) v4(145.34,110.72) v4(145.86,170.85) v4(145.95,115.32) v4(145.95,110.11) v4(146.96,125.97) v4(147.22,115.32) v4(147.22,110.11) v4(148.49,115.32) v4(148.49,110.11) v4(149.38,114.71) v4(149.33,110.69) v4(149.96,115.34) v4(149.91,112.6) v4(149.91,111.33) v4(149.91,110.06) v4(161.29,221.69) v4(163.7,222.33) v4(163.83,186.39) v4(163.83,184.61) v4(169.58,203.4) v4(171.23,230.2) v4(172.11,230.36) v4(173.13,230.2) v4(173.89,230.2) v4(176.43,221.44) v4(178.18,186.77) v4(178.81,186.77) v4(187.61,206.58) v4(193.8,187.66) v5(122.93,121.36) v5(123.06,108.66) v5(125.85,105.87) v5(126.62,120.22) v5(126.74,220.3) v5(127.12,207.09) v5(127.89,214.07) v5(128.01,126.19) v5(130.43,202.9) v5(131.06,167.72) v5(131.19,171.4) v5(132.97,200.61) v5(133.09,103.07) v5(134.62,215.6) v5(135.89,103.2) v5(137.03,212.8) v5(138.5,115.05) v5(138.5,114.03) v5(138.5,113.02) v5(138.5,112) v5(138.5,110.98) v5(138.5,109.97) v5(138.68,137.24) v5(139.7,171.15) v5(139.95,183.59) v5(141.6,181.81) v5(141.88,208.08) v5(142.49,100.53) v5(145.29,206.88) v5(145.41,217.25) v5(146.05,184.61) v5(146.56,218.52) v5(146.56,216.1) v5(146.81,135.33) v5(146.89,106.78) v5(147.83,217.37) v5(148.82,211.43) v5(149.98,190.7) v5(150.59,106.78) v5(150.68,120.12) v5(150.81,121.14) v5(151.23,190.7) v5(152.91,213.82) v5(155.57,222.58) v5(161.29,211.91) v5(161.67,215.72) v5(163.19,224.49) v5(163.19,182.58) v5(164.34,202.9) v5(164.59,181.31) v5(164.97,152.6) v5(165.64,230.33) v5(165.61,180.29) v5(167.54,230.33) v5(167.76,200.61) v5(168.81,230.33) v5(168.81,228.42) v5(173.35,195.78) v5(175.77,205.44) v5(175.77,204.55) v5(176.15,202.9) v5(176.27,201.63) v5(176.27,200.61) v5(176.27,199.34) v5(176.69,207.54) v5(176.69,206.78) v5(176.69,205.82) v5(176.69,205.18) v5(176.69,204.42) v5(176.69,203.53) v5(177.14,158.27) v5(177.67,202.64) v5(177.67,201.75) v5(177.67,200.61) v5(177.67,199.34) v5(177.67,178.13) v5(177.7,203.53) v5(177.8,178.77) v5(178.13,153.24) v5(178.59,207.54) v5(178.59,206.78) v5(178.59,205.82) v5(178.59,205.18) v5(178.59,204.42) v5(178.59,203.53) v5(178.94,202.64) v5(178.94,201.75) v5(178.94,200.61) v5(178.94,199.34) v5(182.37,177.62) v5(182.62,183.08) v5(184.4,182.2) v5(185.07,222.33) v5(185.07,221.69) v5(185.42,177.88) v5(187.23,226.52) v5(187.57,194.52) v5(188.59,178.64) v5(190.24,172.67) v5(190.5,194.64) v5(190.5,181.94) v5(192.4,193.37) v5(192.91,172.29) v5(193.55,166.32) v5(193.67,176.86) v6(124.1,115.04) v6(124.1,112.75) v6(124.33,225.25) v6(124.33,223.6) v6(124.38,198.48) v6(124.38,196.67) v6(124.86,170.03) v6(124.86,168.33) v6(124.84,115.09) v6(124.86,112.75) v6(124.97,141.81) v6(124.99,139.96) v6(125.09,223.47) v6(125.09,198.45) v6(125.07,196.65) v6(125.35,225.25) v6(125.45,115.01) v6(125.63,198.32) v6(125.68,196.67) v6(125.68,170.03) v6(125.68,168.33) v6(125.63,112.83) v6(125.75,141.71) v6(125.85,223.47) v6(125.8,140.06) v6(125.91,115.52) v6(126.29,196.6) v6(126.39,223.28) v6(126.31,198.25) v6(126.46,170.03) v6(126.46,168.33) v6(126.44,141.71) v6(126.59,116.31) v6(126.59,113.18) v6(126.62,225.33) v6(126.62,140.06) v6(126.95,198.15) v6(126.97,196.47) v6(127.05,141.71) v6(127.05,113.79) v6(127.25,225.25) v6(127.21,223.2) v6(127.28,170.03) v6(127.28,168.33) v6(127.28,117.22) v6(127.3,140.06) v6(127.58,198.05) v6(127.66,196.32) v6(127.68,141.71) v6(127.79,118.09) v6(127.79,114.45) v6(127.91,140.06) v6(128.09,170.03) v6(128.09,168.33) v6(128.19,119.2) v6(128.22,197.89) v6(128.29,196.14) v6(128.34,141.84) v6(128.39,115.06) v6(128.48,222.23) v6(128.47,121.49) v6(128.42,120.27) v6(128.52,224.74) v6(128.52,140.13) v6(128.6,122.81) v6(128.7,124.11) v6(128.83,221.54) v6(128.85,170) v6(128.85,168.33) v6(128.9,197.69) v6(128.98,195.91) v6(128.93,142.14) v6(128.98,125.25) v6(128.98,115.77) v6(129.03,220.17) v6(129.03,219.03) v6(129.03,217.76) v6(129.03,216.49) v6(129.03,215.47) v6(129.03,214.45) v6(129.16,213.44) v6(129.16,140.39) v6(129.31,126.27) v6(129.41,212.55) v6(129.41,142.57) v6(129.51,116.61) v6(129.66,224.11) v6(129.66,211.79) v6(129.61,197.44) v6(129.66,170) v6(129.66,168.33) v6(129.72,195.63) v6(129.72,140.64) v6(129.82,143.08) v6(129.84,127.46) v6(129.89,117.73) v6(130.05,211.02) v6(130.27,222.96) v6(130.2,197.21) v6(130.22,143.59) v6(130.2,141.02) v6(130.27,118.8) v6(130.38,195.3) v6(130.43,170.03) v6(130.43,168.33) v6(130.45,128.47) v6(130.48,120.12) v6(130.64,222.09) v6(130.68,210.26) v6(130.68,144.12) v6(130.68,141.43) v6(130.66,122.76) v6(130.63,121.41) v6(130.81,196.93) v6(130.91,221.21) v6(130.96,123.93) v6(131.06,194.92) v6(131.09,141.94) v6(131.04,129.44) v6(131.16,220.19) v6(131.19,217.76) v6(131.19,216.36) v6(131.19,215.09) v6(131.19,214.2) v6(131.11,144.63) v6(131.24,170.03) v6(131.24,168.33) v6(131.32,219.13) v6(131.32,213.31) v6(131.32,209.5) v6(131.39,196.62) v6(131.32,125.22) v6(131.52,145.11) v6(131.54,142.47) v6(131.7,212.42) v6(131.75,194.51) v6(131.72,130.38) v6(131.75,126.32) v6(131.95,208.87) v6(131.95,145.62) v6(132,196.32) v6(132.05,170.03) v6(132.05,168.33) v6(132.08,143.05) v6(132.15,127.23) v6(132.2,211.66) v6(132.33,194.13) v6(132.38,146.13) v6(132.59,208.23) v6(132.56,195.96) v6(132.51,143.56) v6(132.51,131.37) v6(132.69,128.09) v6(132.84,210.9) v6(132.84,193.73) v6(132.81,170) v6(132.81,168.33) v6(132.84,146.66) v6(132.92,144.05) v6(133.04,195.63) v6(133.22,207.6) v6(133.27,147.17) v6(133.27,128.88) v6(133.35,144.55) v6(133.35,132.03) v6(133.47,210.26) v6(133.4,193.22) v6(133.58,195.28) v6(133.63,170) v6(133.63,168.33) v6(133.7,147.65) v6(133.78,145.06) v6(133.86,206.96) v6(133.91,192.71) v6(134.03,194.87) v6(134.01,132.74) v6(134.11,209.63) v6(134.14,148.13) v6(134.19,129.87) v6(134.24,145.59) v6(134.34,192.23) v6(134.49,206.33) v6(134.47,194.49) v6(134.44,170) v6(134.44,168.33) v6(134.54,148.62) v6(134.67,146.1) v6(134.74,208.99) v6(134.8,191.75) v6(134.74,130.43) v6(134.9,194.08) v6(134.85,133.63) v6(135.02,149.13) v6(135.13,205.69) v6(135.1,146.59) v6(135.13,131.01) v6(135.25,191.24) v6(135.23,170) v6(135.23,168.33) v6(135.38,208.36) v6(135.3,193.63) v6(135.53,147.07) v6(135.68,193.24) v6(135.68,190.78) v6(135.68,131.4) v6(135.76,204.93) v6(135.79,134.49) v6(135.91,150.14) v6(135.94,147.55) v6(136.01,207.72) v6(136.07,192.84) v6(136.01,171.43) v6(136.01,170.03) v6(136.01,168.35) v6(136.04,166.88) v6(136.12,190.3) v6(136.47,192.38) v6(136.52,204.29) v6(136.57,132.36) v6(136.65,207.09) v6(136.6,189.79) v6(136.75,135.28) v6(136.83,170.03) v6(136.83,168.35) v6(136.8,151.13) v6(136.88,148.57) v6(137.08,189.28) v6(137.16,203.66) v6(137.16,131.73) v6(137.16,127.54) v6(137.28,206.45) v6(137.26,132.95) v6(137.36,191.39) v6(137.54,188.72) v6(137.64,170.03) v6(137.64,168.33) v6(137.74,152.17) v6(137.77,149.61) v6(137.77,135.94) v6(137.89,190.83) v6(137.92,203.15) v6(138.05,205.82) v6(138.02,188.27) v6(138.15,133.78) v6(138.25,152.71) v6(138.35,190.32) v6(138.43,187.78) v6(138.4,170) v6(138.4,168.33) v6(138.63,150.6) v6(138.76,153.24) v6(138.83,189.82) v6(138.86,187.3) v6(138.89,134.16) v6(138.94,136.55) v6(139.06,171.25) v6(139.16,166.88) v6(139.14,151.11) v6(139.27,189.31) v6(139.22,170) v6(139.22,168.33) v6(139.24,153.75) v6(139.32,204.93) v6(139.32,202.64) v6(139.34,186.79) v6(139.7,154.23) v6(139.65,151.64) v6(139.77,188.8) v6(139.8,186.31) v6(139.92,134.92) v6(140.03,170) v6(140.03,168.33) v6(140.16,154.71) v6(140.16,152.17) v6(140.18,137.24) v6(140.21,188.34) v6(140.28,185.83) v6(140.46,135.08) v6(140.59,202.39) v6(140.61,187.86) v6(140.61,155.17) v6(140.64,152.68) v6(140.76,185.27) v6(140.82,170) v6(140.82,168.33) v6(141.09,204.42) v6(141.09,187.35) v6(141.09,155.65) v6(141.09,153.16) v6(141.2,184.79) v6(141.43,131.62) v6(141.48,127.31) v6(141.55,186.87) v6(141.55,153.65) v6(141.6,202.26) v6(141.6,184.33) v6(141.63,170) v6(141.63,168.33) v6(141.73,156.26) v6(141.88,137.9) v6(141.96,186.41) v6(141.91,135.61) v6(142.06,154.15) v6(142.11,204.42) v6(142.11,183.8) v6(142.19,156.72) v6(142.39,185.98) v6(142.36,157.56) v6(142.49,202.26) v6(142.44,170) v6(142.44,168.33) v6(142.57,183.31) v6(142.82,185.52) v6(142.9,138.25) v6(143,204.42) v6(143,182.86) v6(143.05,136.15) v6(143.13,175.97) v6(143.2,185.07) v6(143.38,169.98) v6(143.38,168.35) v6(143.3,127.26) v6(143.41,182.37) v6(143.51,202.26) v6(143.51,158.47) v6(143.56,155.68) v6(143.51,131.65) v6(143.69,184.61) v6(143.63,138.38) v6(143.76,177.88) v6(143.76,136.35) v6(143.89,204.42) v6(143.91,181.87) v6(143.97,179.15) v6(143.99,158.93) v6(144.07,184.18) v6(144.14,156.26) v6(144.27,177.12) v6(144.4,202.26) v6(144.35,181.38) v6(144.32,138.56) v6(144.45,178.54) v6(144.45,136.45) v6(144.5,183.69) v6(144.63,179.88) v6(144.65,156.8) v6(144.78,204.42) v6(144.93,183.26) v6(144.98,180.7) v6(144.9,176.48) v6(145.08,177.12) v6(145.16,157.43) v6(145.29,182.91) v6(145.24,179.25) v6(145.26,160.15) v6(145.41,175.97) v6(145.59,179.96) v6(145.57,177.66) v6(145.59,156.85) v6(145.57,136.6) v6(145.64,140.97) v6(145.62,138.71) v6(145.72,160.58) v6(145.9,182.53) v6(145.92,202.26) v6(145.92,175.46) v6(146.05,204.42) v6(146.05,178.08) v6(146.15,197.94) v6(146.17,161.04) v6(146.33,182.09) v6(146.47,178.55) v6(146.43,174.83) v6(146.4,170.66) v6(146.48,157.71) v6(146.53,176.76) v6(146.58,176.05) v6(146.58,161.42) v6(146.78,202.26) v6(146.73,181.66) v6(146.71,138.91) v6(146.76,136.88) v6(146.81,155.73) v6(147.06,204.42) v6(147.04,157.15) v6(147.17,176.58) v6(147.19,174.19) v6(147.19,170.64) v6(147.11,162.08) v6(147.24,167.67) v6(147.32,181.05) v6(147.36,158.85) v6(147.47,162.59) v6(147.6,199.44) v6(147.6,161.42) v6(147.57,138.97) v6(147.57,136.86) v6(147.65,176.96) v6(147.65,156.67) v6(147.65,127.61) v6(147.7,131.68) v6(147.83,204.42) v6(147.86,167.11) v6(147.88,162.33) v6(147.85,158.42) v6(147.93,202.26) v6(148,180.6) v6(148.08,173.81) v6(148.25,195.63) v6(148.26,157.95) v6(148.31,177.62) v6(148.31,162.69) v6(148.31,160.71) v6(148.46,171.25) v6(148.59,204.42) v6(148.61,180.14) v6(148.69,157.48) v6(148.77,174.4) v6(148.99,179.63) v6(149.1,202.26) v6(149.07,163.7) v6(149.02,160.02) v6(149.17,200.92) v6(149.18,194.66) v6(149.12,178.44) v6(149.3,159.34) v6(149.48,204.42) v6(149.46,167.39) v6(149.5,174.5) v6(149.65,179.1) v6(149.69,170.67) v6(149.76,195.19) v6(149.73,164.16) v6(149.83,139.19) v6(149.86,137.01) v6(149.98,202.13) v6(149.91,159.06) v6(150.21,178.46) v6(150.26,174.17) v6(150.37,204.42) v6(150.37,185.37) v6(150.37,184.48) v6(150.37,164.54) v6(150.65,178.13) v6(150.75,195.02) v6(150.75,159.26) v6(150.87,202.01) v6(150.87,188.67) v6(151.03,173.86) v6(151.06,170.82) v6(151,137.36) v6(151.13,204.29) v6(151.1,177.57) v6(151.13,139.4) v6(151.25,194.51) v6(151.36,198.77) v6(151.38,165.18) v6(151.51,193.88) v6(151.51,192.99) v6(151.51,192.23) v6(151.51,191.59) v6(151.51,189.05) v6(151.64,197.12) v6(151.89,204.17) v6(151.89,201.75) v6(152.02,196.29) v6(152.29,197.83) v6(152.22,177.07) v6(152.27,161.24) v6(152.27,159.84) v6(152.4,188.67) v6(152.52,195.66) v6(152.68,140.13) v6(152.78,203.79) v6(152.78,201.37) v6(152.7,137.82) v6(153.16,195.02) v6(153.41,194.26) v6(153.41,193.24) v6(153.41,188.67) v6(153.54,192.48) v6(153.54,191.72) v6(153.54,185.75) v6(153.54,184.74) v6(153.52,140.69) v6(153.59,138.25) v6(153.67,203.53) v6(153.64,200.76) v6(153.67,190.83) v6(153.67,190.07) v6(153.67,189.31) v6(153.67,187.78) v6(153.67,186.77) v6(154.28,141.28) v6(154.35,138.71) v6(154.51,199.98) v6(154.55,160.1) v6(154.63,203.1) v6(155.45,202.26) v6(155.42,199.21) v6(155.62,142.47) v6(155.85,139.88) v6(155.95,184.74) v6(155.95,183.85) v6(155.95,182.96) v6(155.95,182.07) v6(155.95,181.26) v6(155.95,180.67) v6(155.95,180.01) v6(156.08,198.35) v6(156.18,143.05) v6(156.28,179.38) v6(156.36,201.45) v6(156.33,185.27) v6(156.44,140.44) v6(156.64,197.36) v6(156.92,200.79) v6(157.1,196.6) v6(157.17,185.83) v6(157.15,185.09) v6(157.17,157.3) v6(157.17,156.69) v6(157.17,155.96) v6(157.2,179.1) v6(157.22,154.76) v6(157.22,153.87) v6(157.35,153.09) v6(157.36,152.12) v6(157.31,150.53) v6(157.35,149.94) v6(157.35,149.18) v6(157.35,148.41) v6(157.35,147.65) v6(157.35,146.89) v6(157.35,146.13) v6(157.35,145.37) v6(157.35,144.6) v6(157.43,200.08) v6(157.45,195.71) v6(157.4,178.26) v6(157.4,177.4) v6(157.48,161.37) v6(157.58,141.53) v6(157.76,194.9) v6(157.96,199.21) v6(157.99,194.26) v6(158.09,185.8) v6(158.27,142.29) v6(158.37,193.55) v6(158.49,192.56) v6(158.49,185.12) v6(158.6,191.57) v6(158.6,187.94) v6(158.62,190.6) v6(158.62,189.84) v6(158.62,188.95) v6(158.62,187.05) v6(158.62,186.11) v6(158.77,197.97) v6(159,151.59) v6(159,150.7) v6(159,149.94) v6(159,149.18) v6(159,148.41) v6(159,147.65) v6(159,146.89) v6(159,146.13) v6(159,145.37) v6(159,144.6) v6(159.09,143.59) v6(159.15,197.28) v6(159.26,113.67) v6(159.46,196.47) v6(159.64,154.47) v6(159.66,153.21) v6(159.66,152.38) v6(159.69,144.71) v6(159.79,150.4) v6(159.76,149.33) v6(159.76,148.46) v6(159.97,195.45) v6(160.2,194.69) v6(160.35,193.98) v6(160.55,193.04) v6(160.53,160.07) v6(160.55,159.23) v6(160.63,192.23) v6(160.6,187.12) v6(160.65,186.26) v6(160.65,185.52) v6(160.65,177.45) v6(160.75,191.39) v6(160.78,190.6) v6(160.7,189.89) v6(160.7,189.1) v6(160.7,188.11) v6(160.78,184.1) v6(160.78,183.21) v6(160.78,178.54) v6(160.88,180.88) v6(160.88,179.86) v6(160.91,182.53) v6(160.93,178) v6(160.93,153.21) v6(160.96,152.38) v6(161.29,156.08) v6(161.28,112.27) v6(161.57,160.68) v6(161.54,155.4) v6(162.05,124.97) v6(162.05,124.21) v6(162.13,104.95) v6(162.43,112.53) v6(162.56,124.97) v6(162.56,124.21) v6(162.56,123.44) v6(164.29,103.15) v6(164.31,106.91) v6(164.31,104.98) v6(165.01,175.95) v6(165.01,174.35) v6(165.01,172.75) v6(165.01,171.15) v6(165.01,167.15) v6(165.01,165.55) v6(165.01,163.95) v6(165.01,162.35) v6(165.73,148.67) v6(165.73,147.65) v6(165.81,175.95) v6(165.81,174.35) v6(165.81,172.75) v6(165.81,171.15) v6(165.81,169.55) v6(165.81,168.75) v6(165.81,167.15) v6(165.81,165.55) v6(165.81,163.95) v6(165.81,162.35) v6(166.83,176.05) v6(167.19,143.84) v6(167.27,151) v6(167.33,169.04) v6(167.41,134.47) v6(167.87,176.05) v6(168.02,160.94) v6(168.12,159.72) v6(168.12,158.75) v6(168.12,157.53) v6(168.27,163.65) v6(168.27,156.19) v6(168.43,155.14) v6(168.4,149.1) v6(168.4,148.34) v6(168.4,141.48) v6(168.4,140.72) v6(168.4,139.95) v6(168.4,132.46) v6(168.4,124.97) v6(168.4,124.21) v6(168.4,123.44) v6(168.91,149.1) v6(168.91,148.34) v6(168.91,147.57) v6(168.91,140.72) v6(168.91,139.95) v6(168.91,132.46) v6(168.91,124.97) v6(168.91,124.21) v6(168.91,123.44) v6(169.09,176.07) v6(169.77,130.66) v6(170.69,176.05) v6(170.69,155.86) v6(170.79,168.73) v6(170.76,164.47) v6(171.09,151.74) v6(171.65,163.48) v6(171.83,168.81) v6(171.91,154) v6(172.08,176.07) v6(172.16,161.37) v6(172.18,159.62) v6(172.36,141.43) v6(172.36,138.46) v6(172.41,146.31) v6(172.67,167.97) v6(172.79,136.25) v6(172.84,145.9) v6(172.84,141.38) v6(172.84,140.24) v6(172.82,138.91) v6(172.82,137.7) v6(173.05,134.67) v6(173.38,164.62) v6(173.33,152.43) v6(173.45,133.45) v6(173.48,130.94) v6(173.48,129.54) v6(173.48,128.07) v6(173.48,126.37) v6(173.48,124.77) v6(173.43,123.12) v6(173.45,121.13) v6(173.56,176.07) v6(173.56,170.36) v6(173.53,167.69) v6(173.63,119.38) v6(173.96,117.93) v6(174.09,162.13) v6(174.11,158.75) v6(174.29,166.7) v6(174.6,172.16) v6(174.52,150.47) v6(174.55,116.64) v6(174.83,176.07) v6(174.98,135.51) v6(175.11,169.34) v6(175.26,165.36) v6(175.28,115.44) v6(175.49,131.93) v6(175.49,122.79) v6(175.51,129.44) v6(175.66,119.58) v6(175.72,171.65) v6(175.89,155.81) v6(175.82,120.35) v6(175.97,118.8) v6(176.1,160.94) v6(176.1,159.39) v6(176.15,173.94) v6(176.2,168.15) v6(176.12,158.09) v6(176.2,114.45) v6(176.32,117.93) v6(176.43,151.33) v6(176.55,160.12) v6(176.68,118.82) v6(176.88,166.73) v6(176.83,116.89) v6(177.14,170.56) v6(177.19,159.23) v6(177.21,173.33) v6(177.29,113.57) v6(177.52,176.07) v6(177.57,129.06) v6(177.52,128.47) v6(177.52,127.18) v6(177.57,125.83) v6(177.59,124.82) v6(177.57,123.83) v6(177.52,122.56) v6(177.62,121.41) v6(177.77,158.73) v6(177.72,117.93) v6(177.87,115.8) v6(177.96,216.86) v6(177.95,169.5) v6(177.95,161.62) v6(178.03,173.97) v6(178.15,172.75) v6(178.26,158.19) v6(178.31,120.55) v6(178.38,112.83) v6(178.41,128.07) v6(178.56,150.27) v6(178.51,148.21) v6(178.51,146.25) v6(178.64,157.38) v6(178.64,156.21) v6(178.64,151.36) v6(178.64,121.13) v6(178.61,119.89) v6(178.71,167.77) v6(178.76,152.71) v6(178.79,149.28) v6(178.74,147.37) v6(178.76,145.34) v6(178.76,143.84) v6(178.76,137.62) v6(178.79,117.4) v6(178.94,136.15) v6(179.02,171.81) v6(179.02,114.94) v6(179.27,163.73) v6(179.25,127.71) v6(179.32,173.76) v6(179.37,134.67) v6(179.32,132.13) v6(179.47,121.92) v6(179.63,112.32) v6(179.7,170.94) v6(179.73,136.55) v6(179.99,215.72) v6(180.03,162.08) v6(180.03,131.8) v6(180.19,170) v6(180.21,119.28) v6(180.34,175.74) v6(180.31,117.12) v6(180.41,141.91) v6(180.49,114.28) v6(180.52,139.07) v6(180.67,173.48) v6(180.62,168.96) v6(180.72,157.35) v6(180.82,167.84) v6(180.82,155.3) v6(180.9,150.5) v6(180.87,147.98) v6(180.82,146.71) v6(180.92,166.68) v6(180.97,149.33) v6(180.97,144.86) v6(180.92,144.12) v6(181.07,151.49) v6(181.05,131.75) v6(181.02,127.59) v6(181.07,119.74) v6(181,111.99) v6(181.1,121.82) v6(181.25,138.15) v6(181.3,135.99) v6(181.46,129.62) v6(181.56,139.12) v6(181.71,141.71) v6(181.84,173.03) v6(181.89,117.15) v6(181.94,131.62) v6(181.96,119.23) v6(182.07,159.69) v6(182.22,150.27) v6(182.24,113.95) v6(182.42,158.75) v6(182.47,127.56) v6(182.47,111.81) v6(182.7,157.86) v6(182.78,139.4) v6(182.78,138.08) v6(182.8,172.62) v6(182.8,156.8) v6(182.8,155.48) v6(182.83,154.56) v6(182.83,153.37) v6(182.83,141.61) v6(182.88,135.92) v6(182.85,121.79) v6(182.95,119.71) v6(183.03,152.45) v6(183.16,174.83) v6(183.13,161.52) v6(183.13,158.6) v6(183.28,131.65) v6(183.46,117.12) v6(183.77,151.89) v6(183.74,149.81) v6(183.84,157.79) v6(183.89,127.56) v6(183.82,113.92) v6(183.87,111.84) v6(184,119.2) v6(184.05,139.37) v6(184.17,171.71) v6(184.15,160.56) v6(184.22,141.63) v6(184.25,138.05) v6(184.43,174.12) v6(184.43,121.77) v6(184.58,131.68) v6(184.66,154.84) v6(184.61,153.98) v6(184.61,151.69) v6(184.61,149.46) v6(184.76,117.1) v6(184.88,152.94) v6(184.83,119.69) v6(184.99,135.79) v6(185.09,144.53) v6(185.11,148.54) v6(185.14,147.22) v6(185.19,145.75) v6(185.34,170.87) v6(185.32,127.38) v6(185.34,111.81) v6(185.54,151.94) v6(185.54,143.05) v6(185.6,141.51) v6(185.52,113.95) v6(185.62,173.38) v6(185.7,151.18) v6(185.67,119.18) v6(185.77,131.65) v6(185.93,137.8) v6(186.03,158.68) v6(186.08,121.77) v6(186.1,126.6) v6(186.13,117.1) v6(186.21,169.95) v6(186.36,142.37) v6(186.33,135.08) v6(186.48,129.41) v6(186.51,119.69) v6(186.61,157.71) v6(186.69,156.54) v6(186.61,150.88) v6(186.69,150.14) v6(186.74,172.47) v6(186.74,155.81) v6(186.76,154.81) v6(186.87,153.65) v6(186.87,111.86) v6(186.94,169.24) v6(186.97,137.09) v6(186.92,113.92) v6(187.17,148.72) v6(187.17,125.68) v6(187.25,147.19) v6(187.22,145.44) v6(187.22,142.04) v6(187.37,137.95) v6(187.37,128.4) v6(187.35,119.23) v6(187.48,149.99) v6(187.42,117.1) v6(187.55,171.71) v6(187.5,134.9) v6(187.68,168.25) v6(187.65,152.83) v6(187.65,121.79) v6(187.88,159.46) v6(187.88,157.86) v6(187.88,156.36) v6(187.83,131.62) v6(187.86,129.52) v6(187.98,155.53) v6(188.01,127.74) v6(188.16,167.34) v6(188.26,170.97) v6(188.26,149.02) v6(188.26,137.01) v6(188.36,154.61) v6(188.36,152.05) v6(188.36,147.78) v6(188.39,125.1) v6(188.44,146.51) v6(188.59,137.59) v6(188.59,119.74) v6(188.72,127.31) v6(188.75,117.1) v6(188.87,170.23) v6(188.87,166.22) v6(188.87,153.9) v6(188.9,144.53) v6(188.82,134.88) v6(188.85,119.2) v6(189.02,121.79) v6(189.08,111.99) v6(189.13,151.33) v6(189.25,145.42) v6(189.38,164.9) v6(189.66,163.35) v6(189.61,152.91) v6(189.66,151.67) v6(189.61,129.52) v6(189.74,169.06) v6(189.74,137.44) v6(189.81,150.62) v6(189.94,134.85) v6(189.91,126.95) v6(189.94,124.84) v6(190.02,136.98) v6(190.14,144.22) v6(190.19,140.34) v6(190.12,111.71) v6(190.27,119.71) v6(190.45,167.84) v6(190.47,155.4) v6(190.45,149.07) v6(190.5,147.93) v6(190.45,147.27) v6(190.42,145.01) v6(190.47,121.74) v6(190.96,134.75) v6(190.98,131.98) v6(190.98,129.85) v6(191.06,143.59) v6(191.11,166.47) v6(191.16,154.48) v6(191.11,150.14) v6(191.13,127.03) v6(191.23,138.58) v6(191.21,124.54) v6(191.29,118.21) v6(191.34,137.47) v6(191.31,111.89) v6(191.49,165.2) v6(191.44,113.87) v6(191.46,113.06) v6(191.69,153.34) v6(191.72,139.52) v6(191.82,164.01) v6(191.84,162.43) v6(191.84,161.06) v6(191.84,159.72) v6(191.82,142.7) v6(192.05,158.75) v6(192.07,157.81) v6(192.05,134.49) v6(192.07,127.33) v6(192.17,124.39) v6(192.28,149.79) v6(192.2,132.39) v6(192.45,154.97) v6(192.4,152.58) v6(192.48,129.64) v6(192.56,156.34) v6(192.56,151.26) v6(192.66,141.02) v6(192.61,130.99) v6(192.66,125.43) v6(192.73,157.08) v6(192.76,136.86) v6(192.76,135.33) v6(192.71,126.29) v8(119.18,225.24) v8(119.18,223.56) v8(119.18,211.74) v8(119.18,210.06) v8(119.12,198.4) v8(119.12,196.72) v8(119.12,184.94) v8(119.12,183.26) v8(119.12,170) v8(119.12,168.33) v8(119.12,156.62) v8(119.12,154.94) v8(119.12,141.76) v8(119.12,140.08) v8(119.18,128.24) v8(119.18,126.56) v8(119.18,114.74) v8(119.18,113.06) v8(120.39,198.4) v8(120.39,196.72) v8(120.39,184.94) v8(120.39,183.26) v8(120.39,170) v8(120.39,168.33) v8(120.39,156.62) v8(120.39,154.94) v8(120.39,141.76) v8(120.39,140.08) v8(120.45,225.24) v8(120.45,223.56) v8(120.45,211.74) v8(120.45,210.06) v8(120.45,128.24) v8(120.45,126.56) v8(120.45,114.74) v8(120.45,113.06) v8(121.66,198.4) v8(121.66,196.72) v8(121.66,184.94) v8(121.66,183.26) v8(121.66,170) v8(121.66,168.33) v8(121.66,156.62) v8(121.66,154.94) v8(121.66,141.76) v8(121.66,140.08) v8(121.72,225.24) v8(121.72,223.56) v8(121.72,211.74) v8(121.72,210.06) v8(121.72,128.24) v8(121.72,126.56) v8(121.72,114.74) v8(121.72,113.06) v8(122.99,225.24) v8(122.99,223.56) v8(122.99,211.74) v8(122.99,210.06) v8(122.93,198.4) v8(122.93,196.72) v8(122.93,184.94) v8(122.93,183.26) v8(122.93,170) v8(122.93,168.33) v8(122.93,156.62) v8(122.93,154.94) v8(122.93,141.76) v8(122.93,140.08) v8(122.99,128.24) v8(122.99,126.56) v8(122.99,114.74) v8(122.99,113.06)
